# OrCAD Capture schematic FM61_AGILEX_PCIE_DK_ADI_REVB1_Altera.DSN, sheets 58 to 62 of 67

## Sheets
58 PWR - VCC_HSSI: size Custom
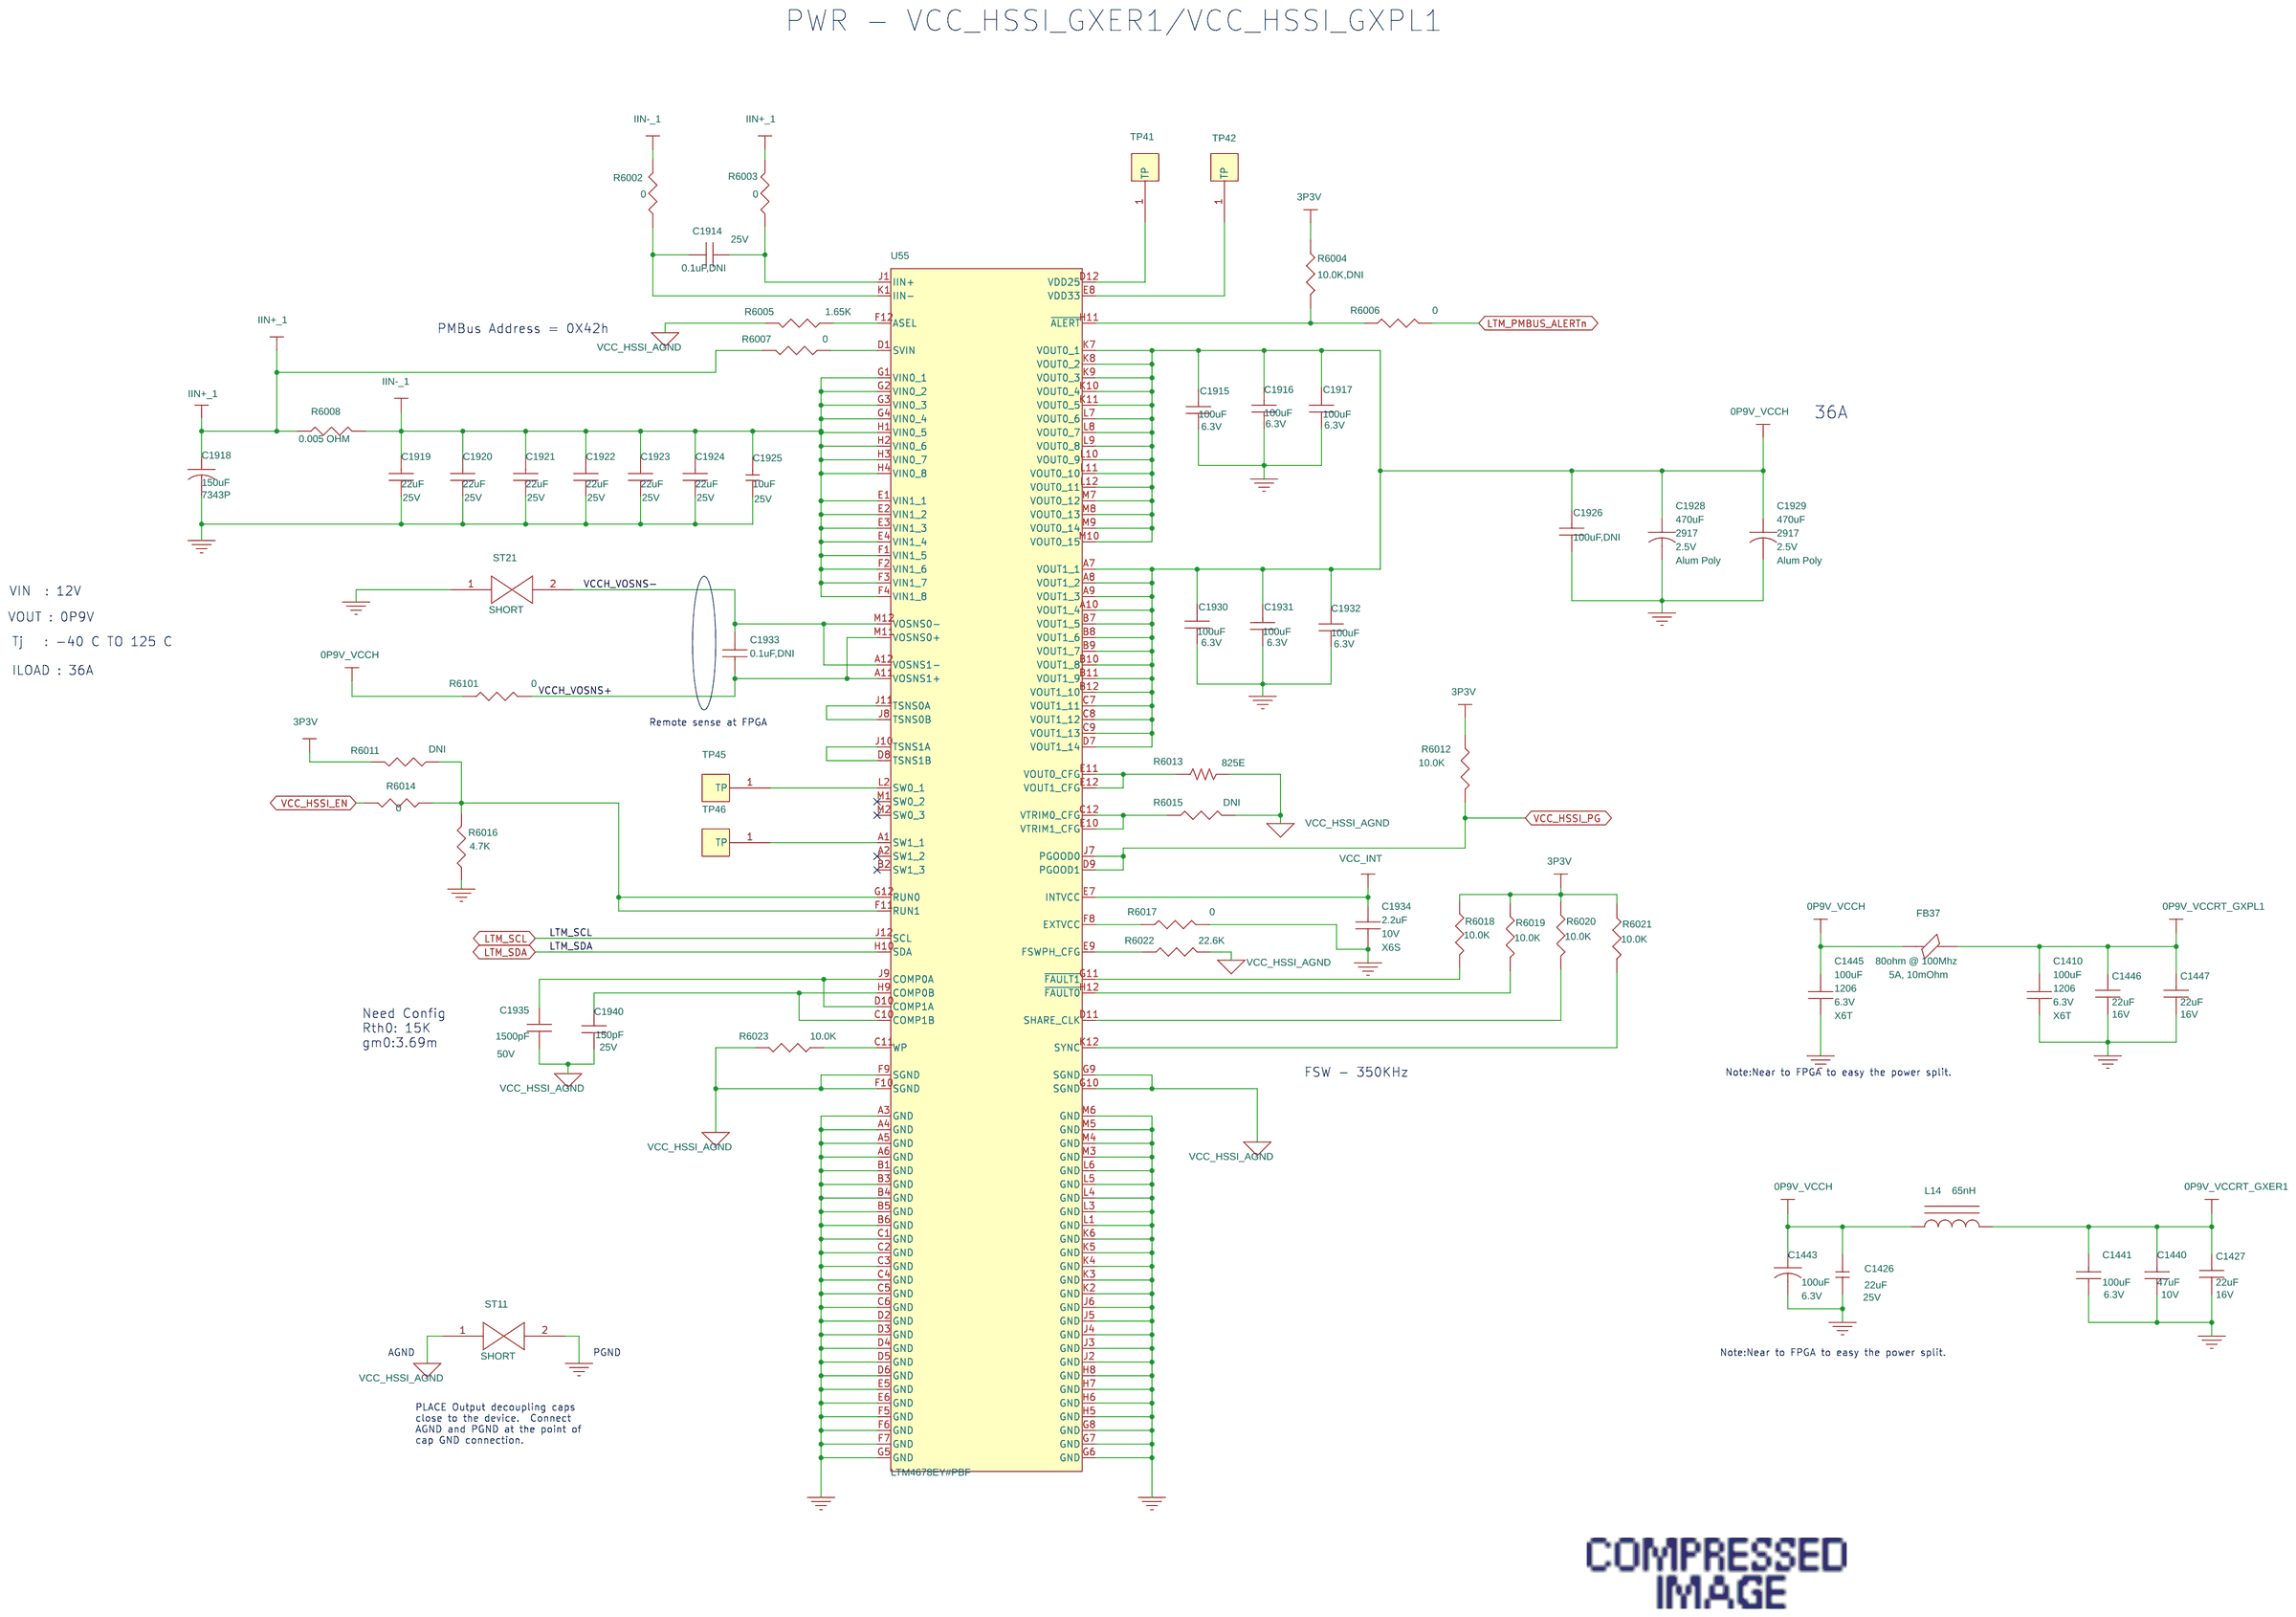
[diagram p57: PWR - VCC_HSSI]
59 PWR - 1p2V_VCCR: size B
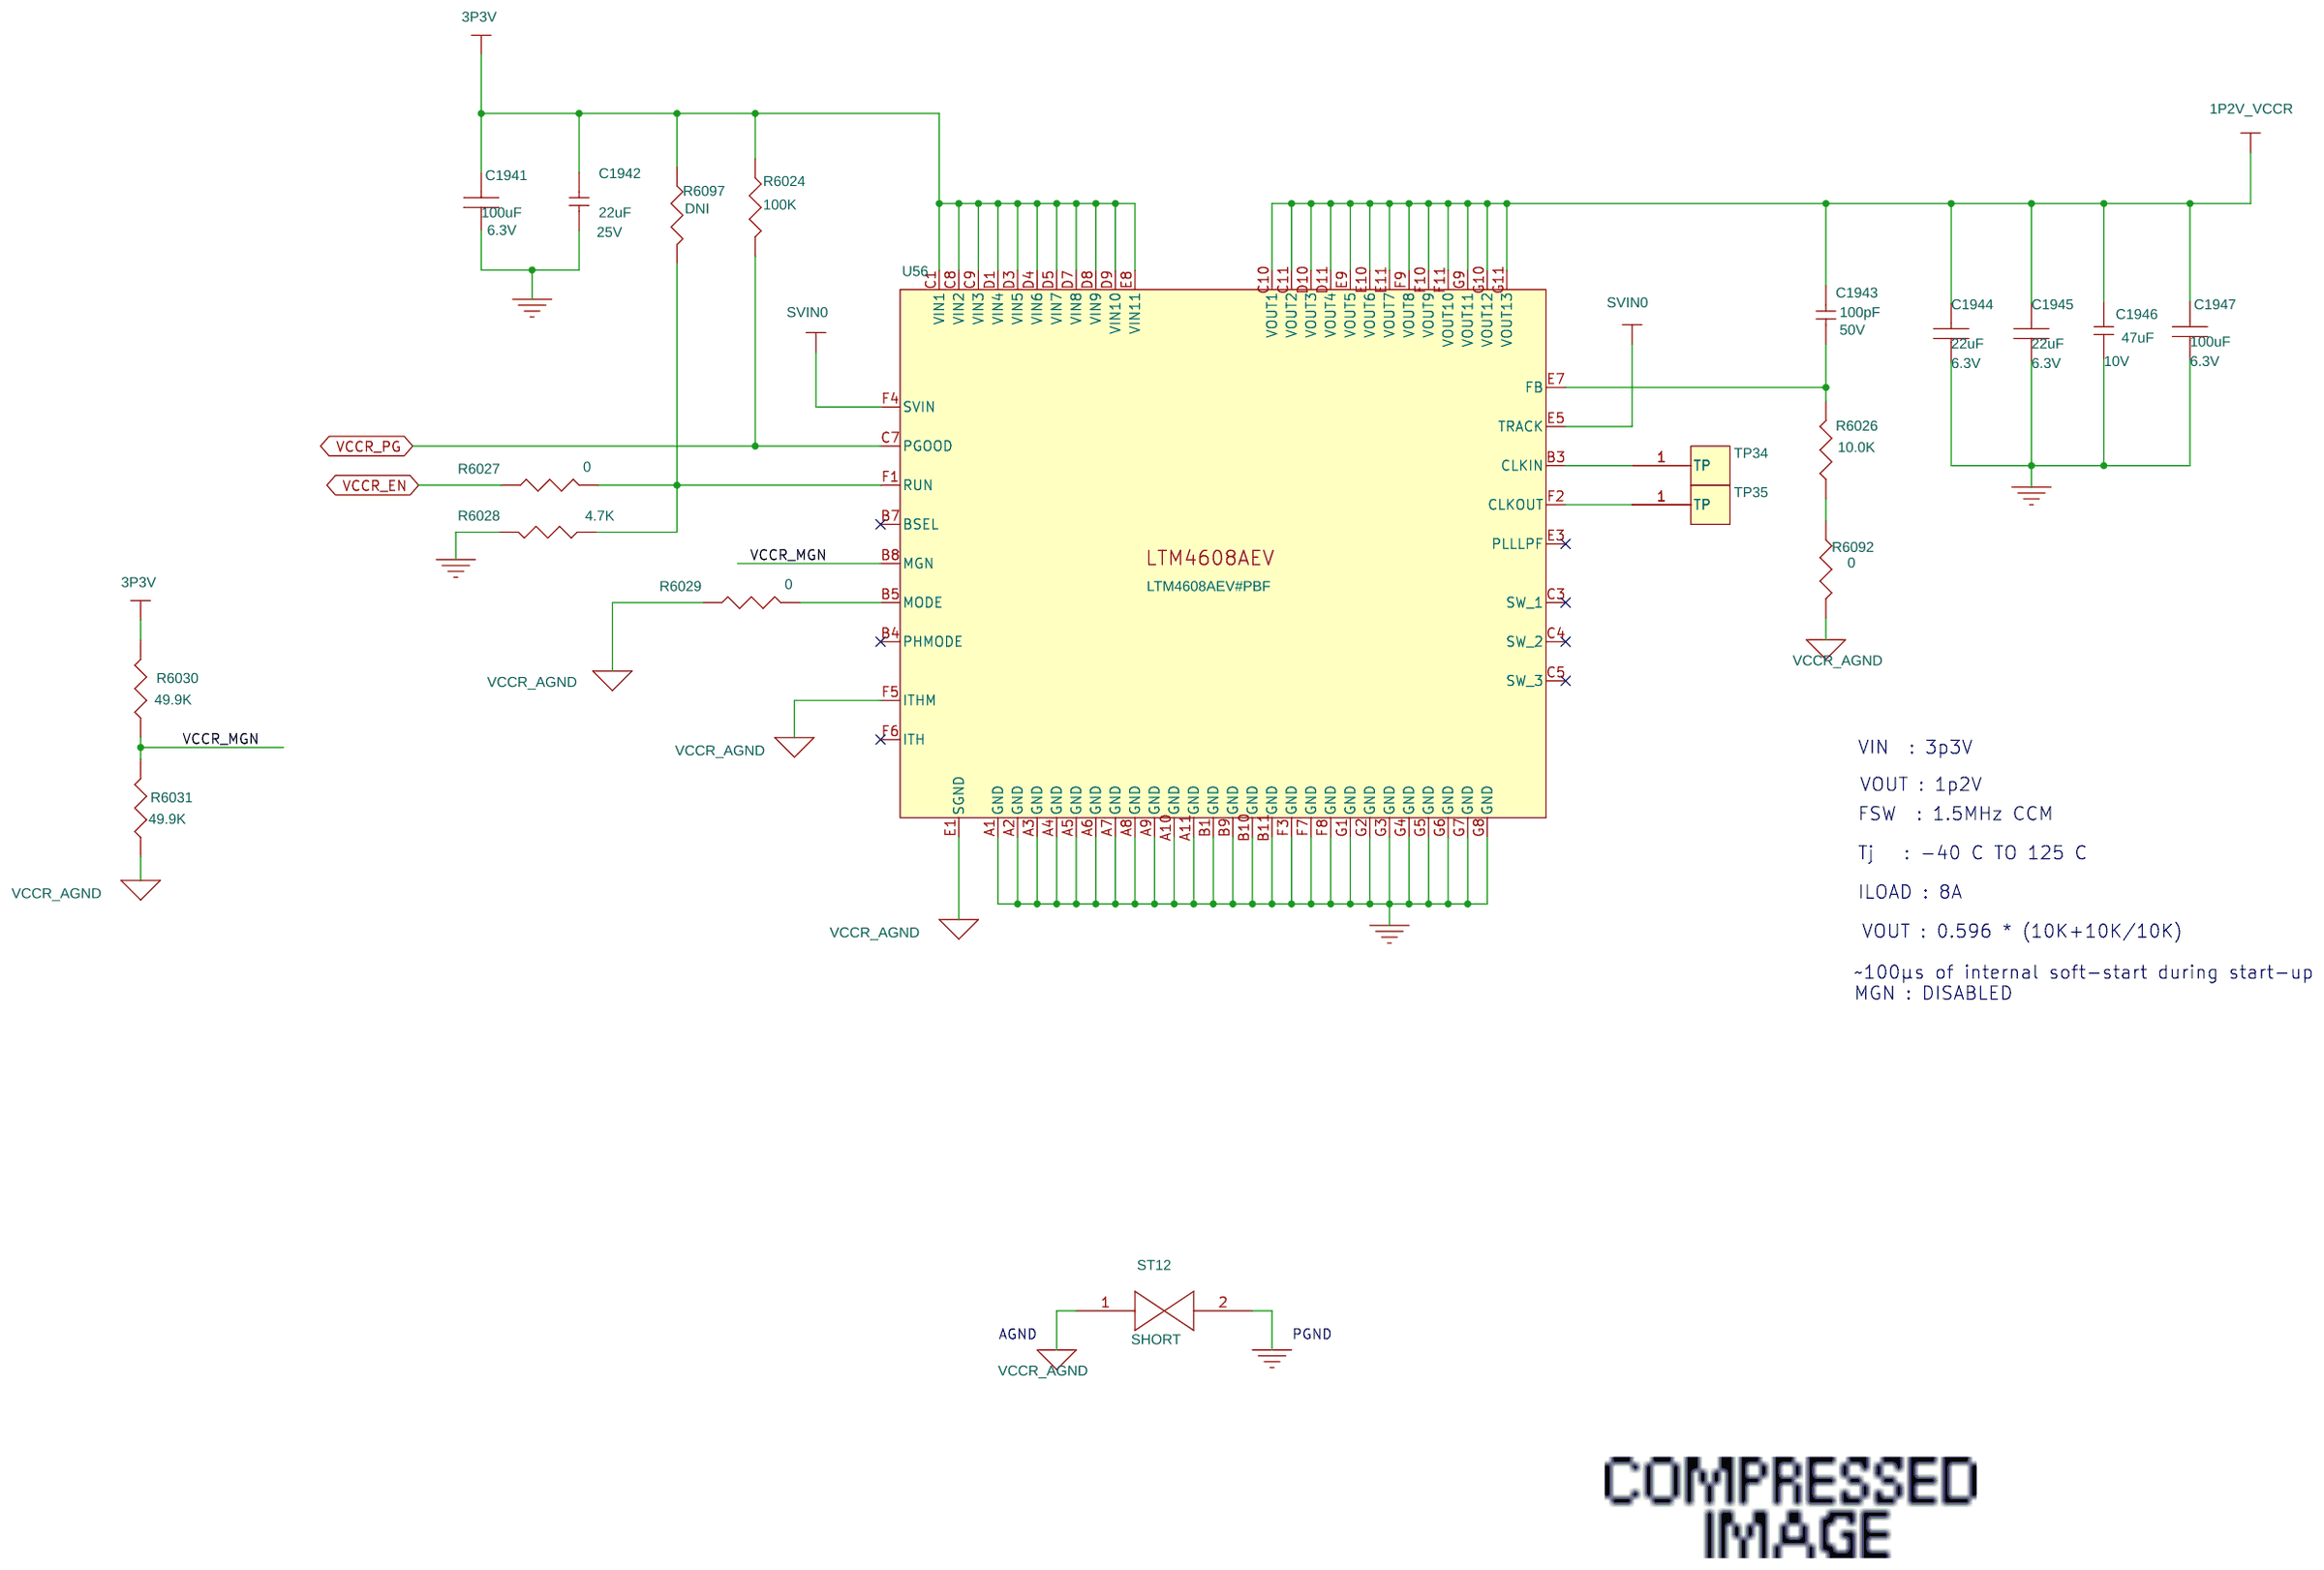
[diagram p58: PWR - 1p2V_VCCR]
60 PWR - 1p2V_DDR4_CH01: size B
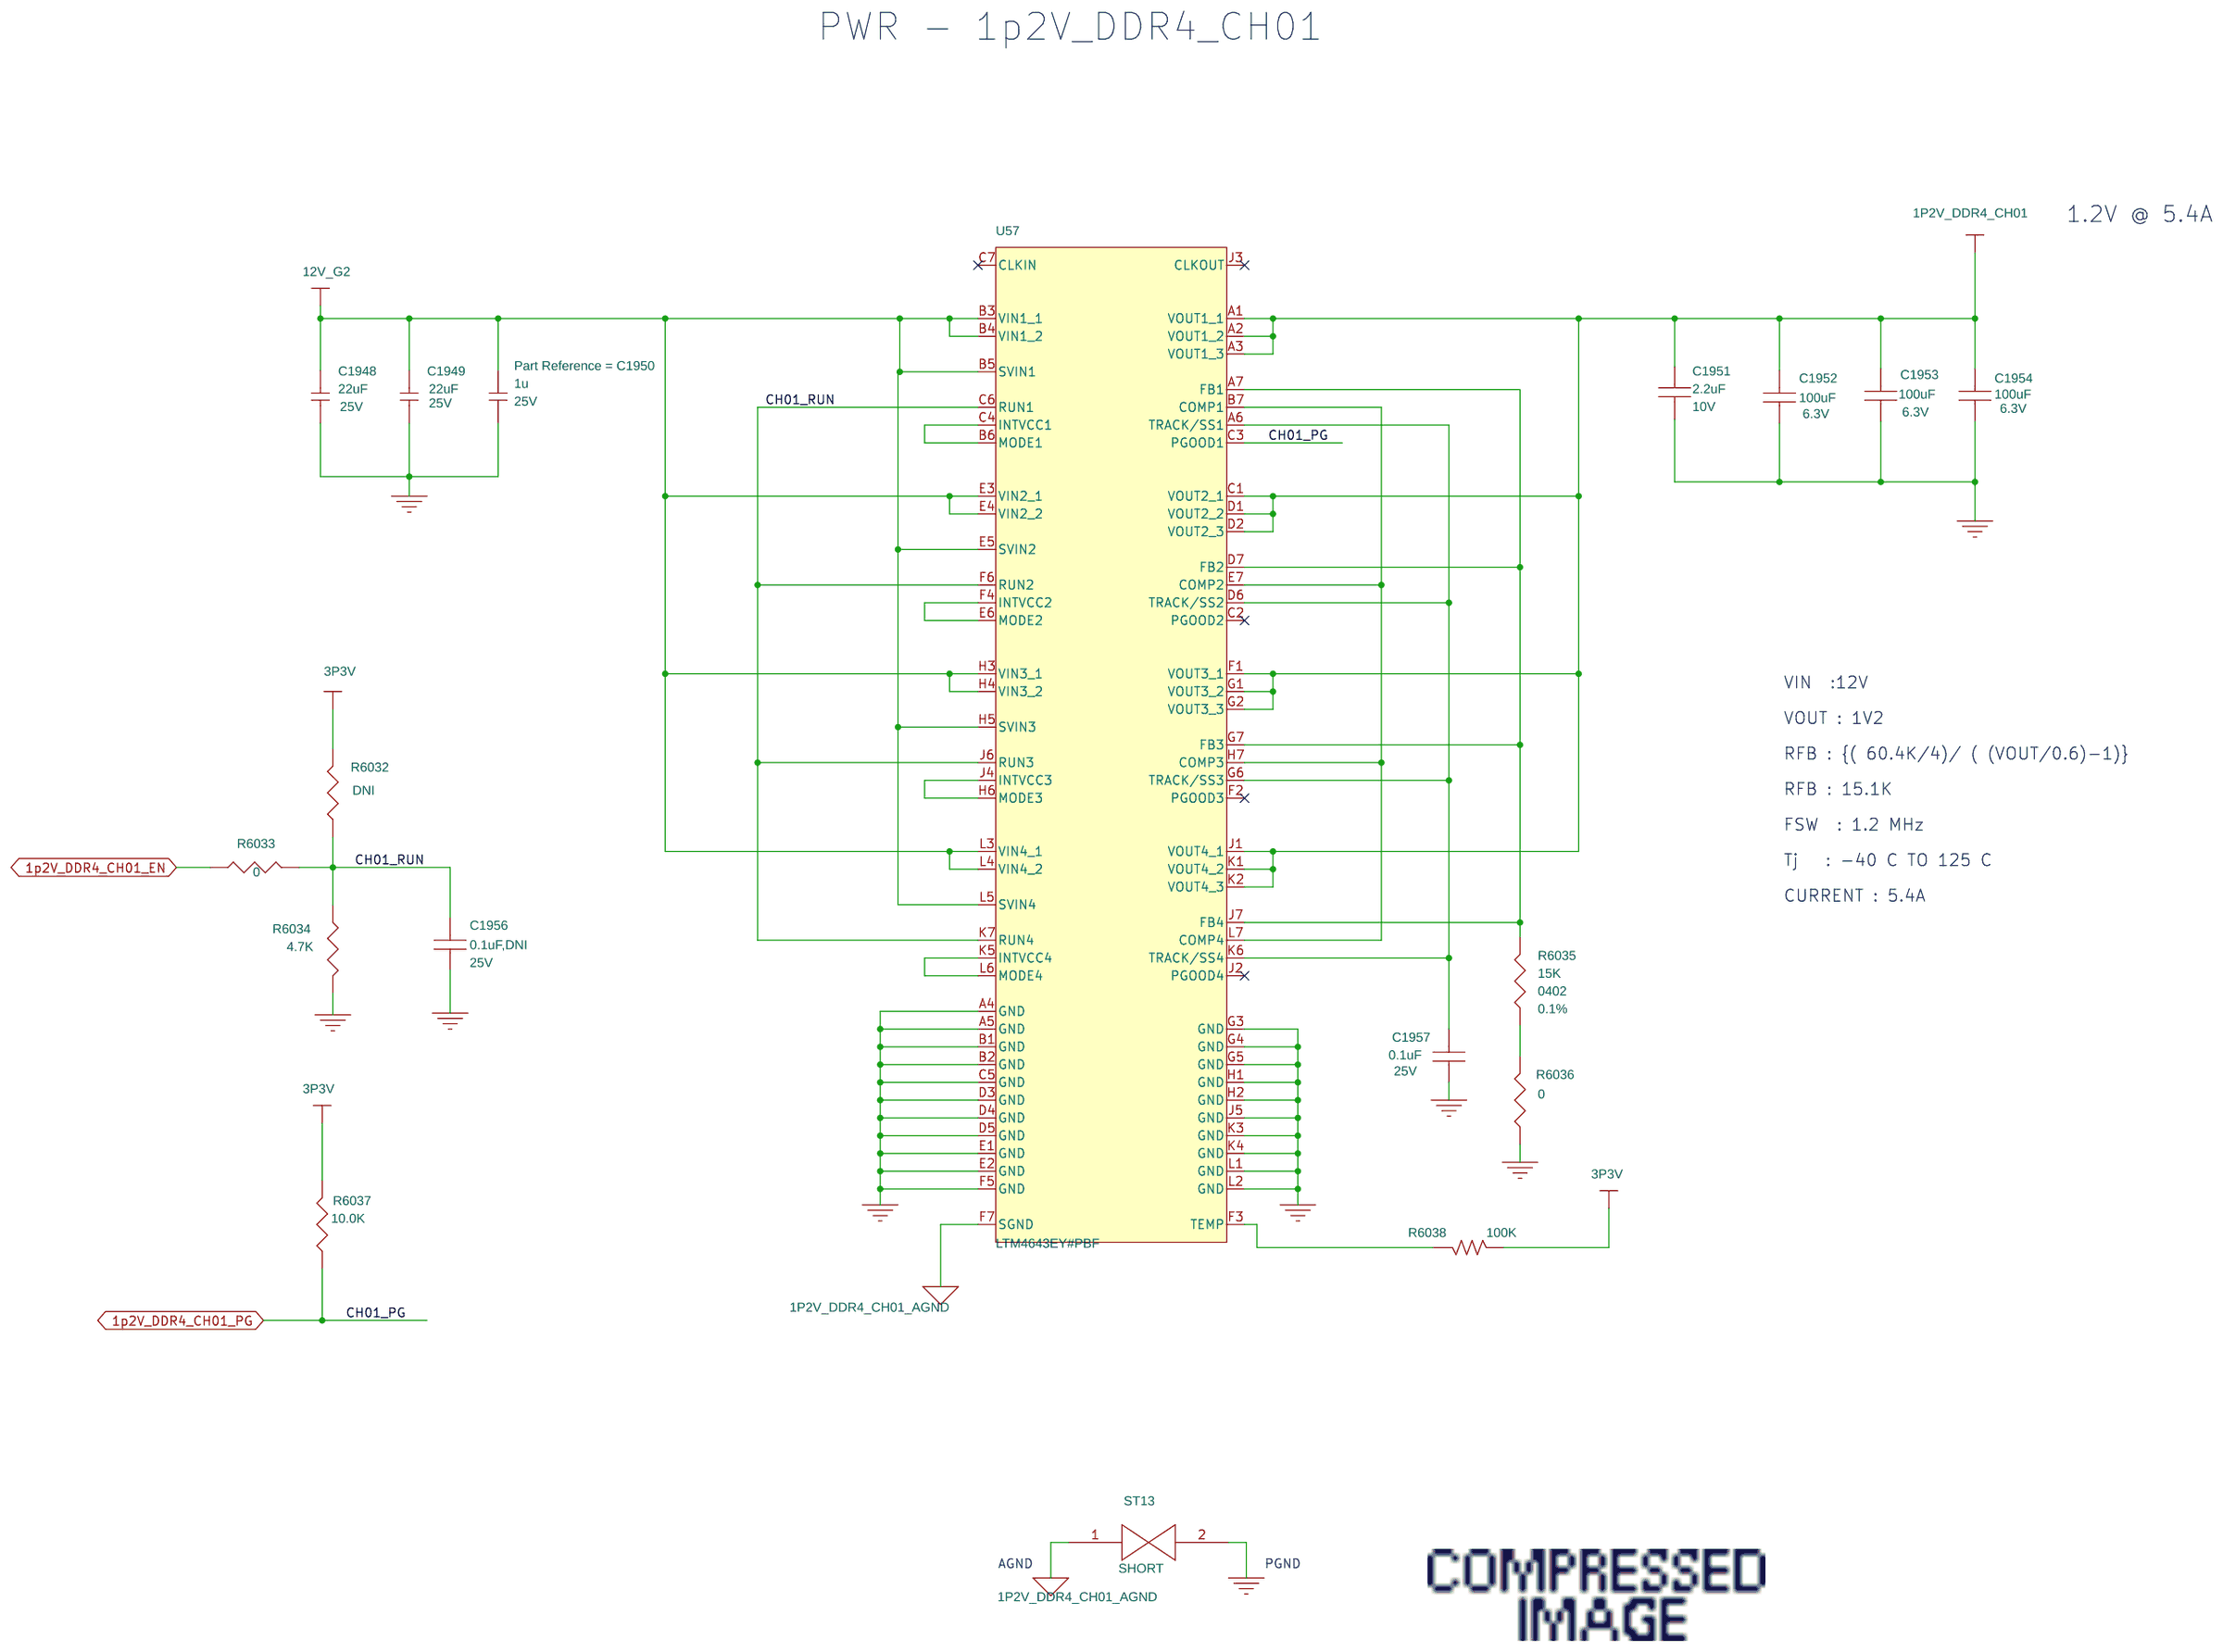
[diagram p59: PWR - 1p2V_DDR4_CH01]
61 PWR - 1p2V_DDR4_CH23: size B
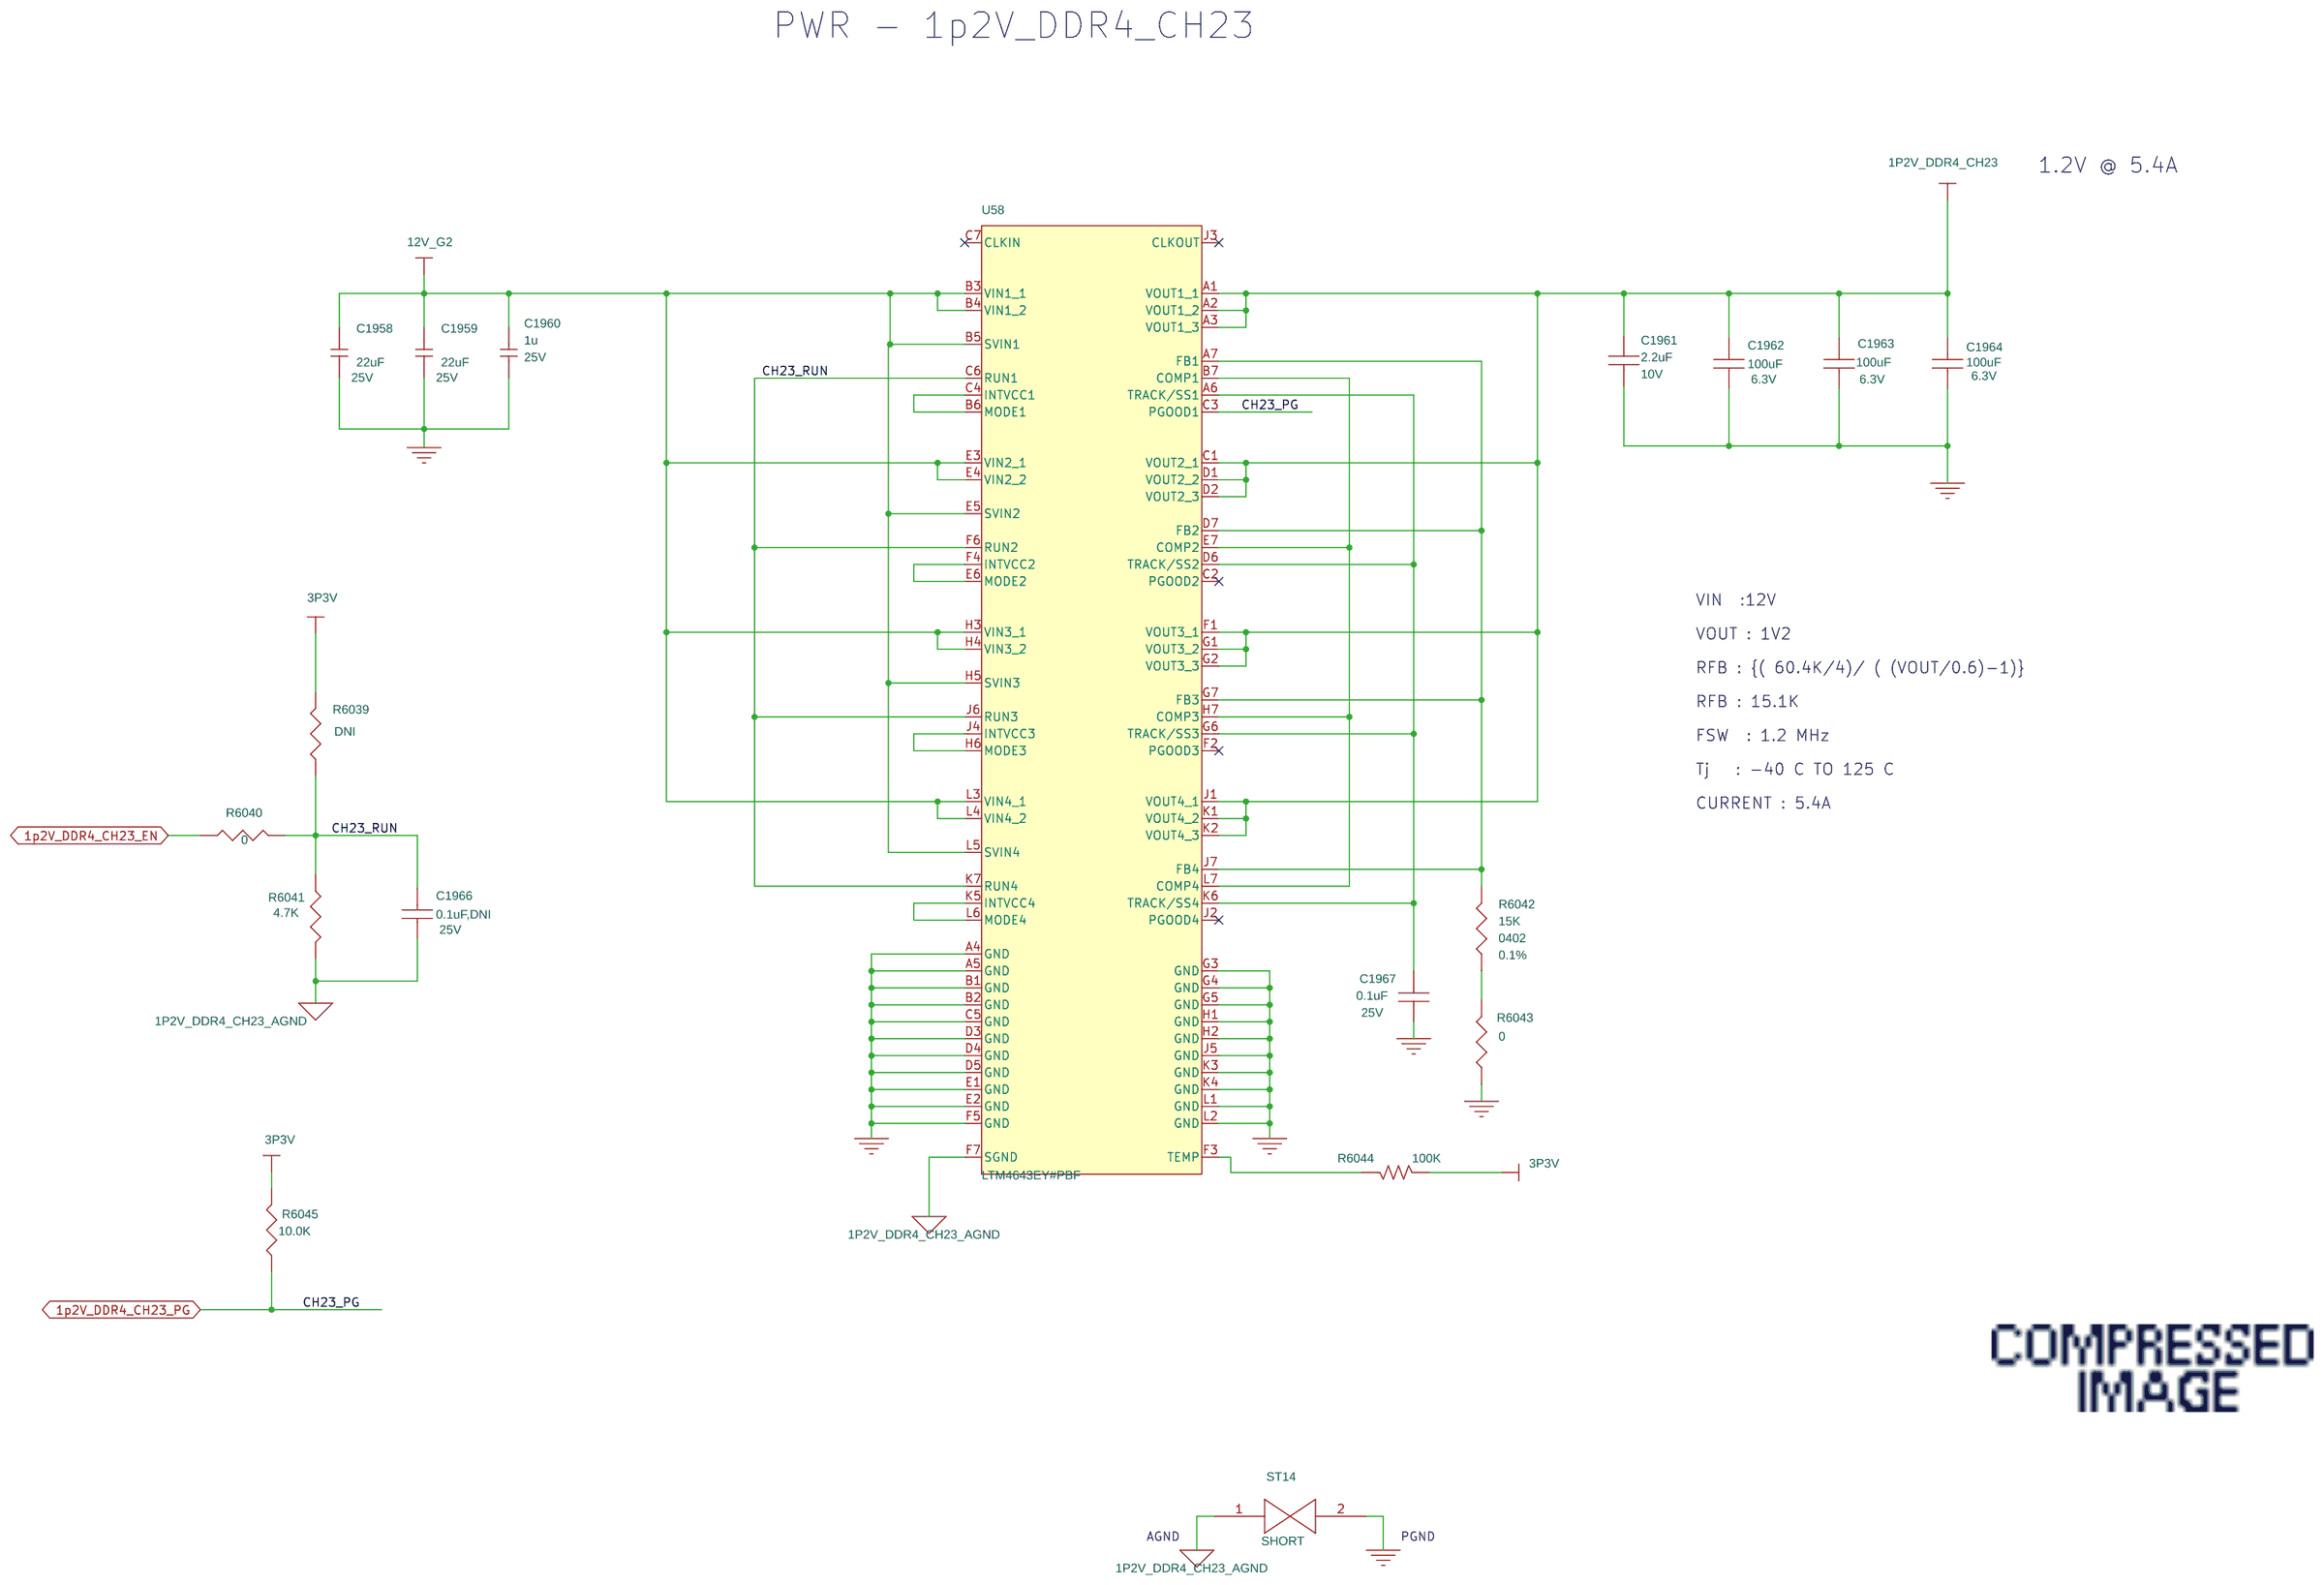
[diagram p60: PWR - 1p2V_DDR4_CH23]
62 PWR - 0p6V_VTT/VREF: size B
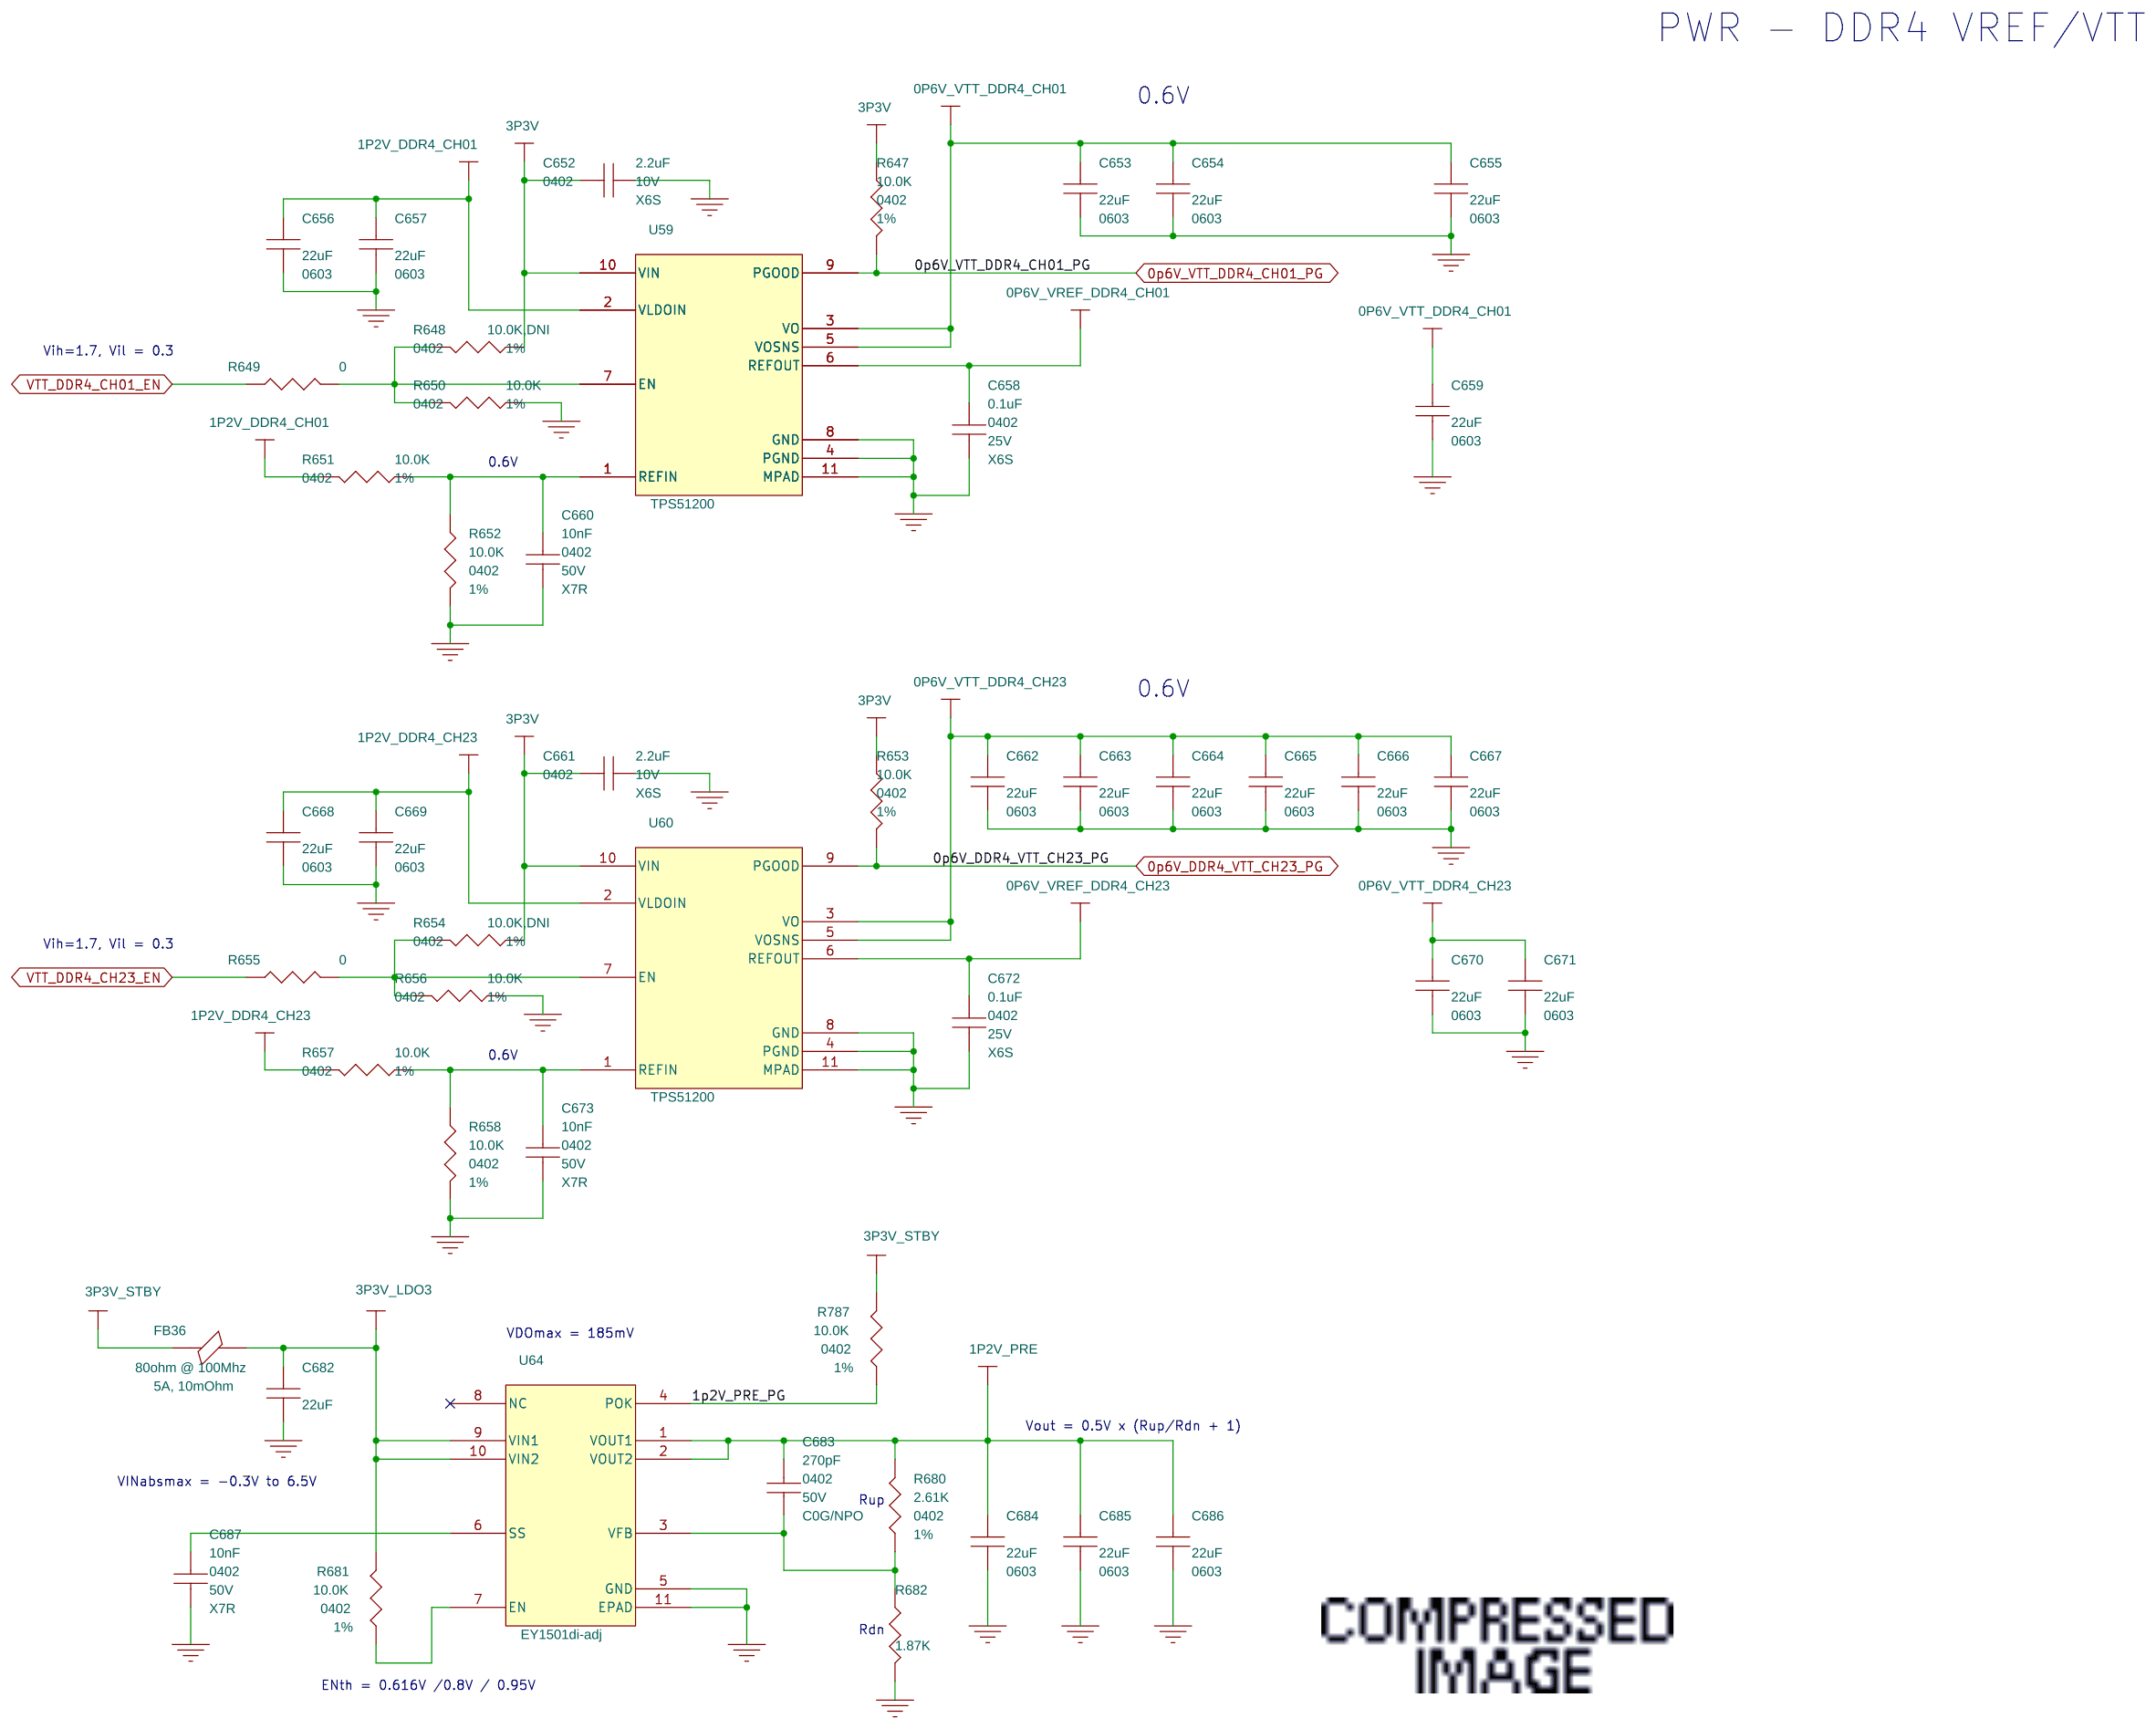
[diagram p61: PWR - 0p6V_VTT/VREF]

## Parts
sheet PWR - 0p6V_VTT/VREF
C652  2.2uF  [0402]
C653  22uF  [0603]
C654  22uF  [0603]
C655  22uF  [0603]
C656  22uF  [0603]
C657  22uF  [0603]
C658  0.1uF  [0402]
C659  22uF  [0603]
C660  10nF  [0402]
C661  2.2uF  [0402]
C662  22uF  [0603]
C663  22uF  [0603]
C664  22uF  [0603]
C665  22uF  [0603]
C666  22uF  [0603]
C667  22uF  [0603]
C668  22uF  [0603]
C669  22uF  [0603]
C670  22uF  [0603]
C671  22uF  [0603]
C672  0.1uF  [0402]
C673  10nF  [0402]
C682  22uF  [0603]
C683  270pF  [0402]
C684  22uF  [0603]
C685  22uF  [0603]
C686  22uF  [0603]
C687  10nF  [0402]
FB36  80ohm @ 100Mhz  [0805]
R647  10.0K  [0402]
R648  10.0K,DNI  [0402]
R649  0  [0402]
R650  10.0K  [0402]
R651  10.0K  [0402]
R652  10.0K  [0402]
R653  10.0K  [0402]
R654  10.0K,DNI  [0402]
R655  0  [0402]
R656  10.0K  [0402]
R657  10.0K  [0402]
R658  10.0K  [0402]
R680  2.61K  [0402]
R681  10.0K  [0402]
R682  1.87K  [0402]
R787  10.0K  [0402]
U59  TPS51200  [VSON-11]
U60  TPS51200  [VSON-11]
U64  EY1501di-adj  [DFN-11]
sheet PWR - 1p2V_DDR4_CH01
C1948  22uF  [1206]
C1949  22uF  [1206]
C1950  1u  [capc1005x60l20l]
C1951  2.2uF  [CC0603N]
C1952  100uF  [1206]
C1953  100uF  [1206]
C1954  100uF  [1206]
C1956  0.1uF,DNI  [0402]
C1957  0.1uF  [0402]
R6032  DNI  [0402]
R6033  0  [0402]
R6034  4.7K  [0402]
R6035  15K  [0402]
R6036  0  [0402]
R6037  10.0K  [0402]
R6038  100K  [R0402]
ST13  SHORT  [SHORT]
U57  LTM4643EY#PBF  [BGA77C127P7X11_900X1500X262N]
sheet PWR - 1p2V_DDR4_CH23
C1958  22uF  [1206]
C1959  22uF  [1206]
C1960  1u  [capc1005x60l20l]
C1961  2.2uF  [CC0603N]
C1962  100uF  [1206]
C1963  100uF  [1206]
C1964  100uF  [1206]
C1966  0.1uF,DNI  [0402]
C1967  0.1uF  [0402]
R6039  DNI  [0402]
R6040  0  [0402]
R6041  4.7K  [0402]
R6042  15K  [0402]
R6043  0  [0402]
R6044  100K  [R0402]
R6045  10.0K  [0402]
ST14  SHORT  [SHORT]
U58  LTM4643EY#PBF  [BGA77C127P7X11_900X1500X262N]
sheet PWR - 1p2V_VCCR
C1941  100uF  [1206]
C1942  22uF  [1206]
C1943  100pF  [0402]
C1944  22uF  [0603]
C1945  22uF  [0603]
C1946  47uF  [1206]
C1947  100uF  [1206]
R6024  100K  [0402]
R6026  10.0K  [0402]
R6027  0  [0402]
R6028  4.7K  [0402]
R6029  0  [0402]
R6030  49.9K  [0402]
R6031  49.9K  [0402]
R6092  0  [0402]
R6097  DNI  [0402]
ST12  SHORT  [SHORT]
TP34  TESTPOINT  [30mil_TP]
TP35  TESTPOINT  [30mil_TP]
U56  LTM4608AEV#PBF  [LGA68S127P7X11_900X1500X292]
sheet PWR - VCC_HSSI
C1410  100uF  [1206]
C1426  22uF  [1206]
C1427  22uF  [0805]
C1440  47uF  [0805]
C1441  100uF  [0805]
C1443  100uF  [B2]
C1445  100uF  [1206]
C1446  22uF  [0805]
C1447  22uF  [0805]
C1914  0.1uF,DNI  [0402]
C1915  100uF  [1206]
C1916  100uF  [1206]
C1917  100uF  [1206]
C1918  150uF  [7343P]
C1919  22uF  [1206]
C1920  22uF  [1206]
C1921  22uF  [1206]
C1922  22uF  [1206]
C1923  22uF  [1206]
C1924  22uF  [1206]
C1925  10uF  [1206]
C1926  100uF,DNI  [1206]
C1928  470uF  [2917]
C1929  470uF  [2917]
C1930  100uF  [1206]
C1931  100uF  [1206]
C1932  100uF  [1206]
C1933  0.1uF,DNI  [0402]
C1934  2.2uF  [0402]
C1935  1500pF  [0402]
C1940  150pF  [0402]
FB37  80ohm @ 100Mhz  [0805]
L14  65nH  [SL1616A-R06LU]
R6002  0  [0402]
R6003  0  [0402]
R6004  10.0K,DNI  [0402]
R6005  1.65K  [0402]
R6006  0  [0402]
R6007  0  [0402]
R6008  0.005 OHM  [RES_CSNL2512_0_005-0_006]
R6011  DNI  [0402]
R6012  10.0K  [0402]
R6013  825E  [0402]
R6014  0  [0402]
R6015  DNI  [0402]
R6016  4.7K  [0402]
R6017  0  [0402]
R6018  10.0K  [0402]
R6019  10.0K  [0402]
R6020  10.0K  [0402]
R6021  10.0K  [0402]
R6022  22.6K  [0402]
R6023  10.0K  [0402]
R6101  0  [0402]
ST11  SHORT  [SHORT]
ST21  SHORT  [SHORT]
TP41  TESTPOINT  [30mil_TP]
TP42  TESTPOINT  [30mil_TP]
TP45  TESTPOINT  [30mil_TP]
TP46  TESTPOINT  [30mil_TP]
U55  LTM4678EY#PBF  [BGA144C127P12X12_1600X1600X626]

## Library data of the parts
C652 C661 = CAP: CAP CER 2.2UF 10V X6S 0402; Dielectric: X6S; IPN: H90637-001; IPN No: H90637-001; Item Num: P03-17966R; LIFECYCLE_PHASE: Active; Lead Free Status: Lead Free; Manufacturer: Murata; Manufacturer Part Num: GRM155C81A225KE44D; Num Pins: 2; Part Class: CAPACITORS; RATED_VOLTAGE: 10V; RoHS Compliant: RoHS Compliant; Tolerance: 10%
C653-C657 C659 C662-C671 C684-C686 = CAP: CAP CER 22UF 6.3V X6S 0603; AGILE_LINK: http://sj-agile9app/Agile/PLMServlet?action=OpenEmailObject&classid=10000&objid=257560276; IPN: H63299-001; Item Num: P03-17963R; LIFECYCLE_PHASE: Active; Lead Free Status: Lead Free; MFR_LIFECYCLE: Active; Manufacturer: Murata; Manufacturer Part Num: GRM188C80J226ME15D; Num Pins: 2; PART_SUBCLASS: CAPACITORS; RATED_VOLTAGE: 6.3V; RoHS Compliant: RoHS Compliant; TOLERANCE: 20%; Temperature Coefficient: X6S
C658 C672 = CAP: CAP CER 0.1UF 25V X6S 0402; Dielectric: X6S; IPN: K19434-001; IPN No: K19434-001; Item Num: P03-17989R; LIFECYCLE_PHASE: Active; Lead Free Status: Lead Free; Manufacturer: Murata; Manufacturer Part Num: GRM155C81E104KA12D; Num Pins: 2; Part Class: CAPACITORS; RATED_VOLTAGE: 25V; RoHS Compliant: RoHS Compliant; Tolerance: 10%
C660 C673 C687 = CAP: CAP - CER, 10NF, 50V, +/-10%, X7R, 0402 SMD; CAPACITANCE: 0.1uF; Dielectric: X7R; IPN: A36096-100; Item Num: P03-16318R; LIFECYCLE_PHASE: Active; Lead Free Status: Lead Free; Manufacturer: Murata; Manufacturer Part Num: GRM155R71H103KA88D; Num Pins: 2; Part Class: CAPACITORS; RATED_VOLTAGE: 50V; RoHS Compliant: RoHS Compliant; Tolerance: 10%
C682 = CAP: CAP CER 22UF 6.3V X6S 0603; AGILE_LINK: http://sj-agile9app/Agile/PLMServlet?action=OpenEmailObject&classid=10000&objid=257560276; IPN: H63299-001; Item Num: P03-17963R; LIFECYCLE_PHASE: Active; Lead Free Status: Not Lead Free; MFR_LIFECYCLE: Active; Manufacturer: Murata; Manufacturer Part Num: GRM188C80J226ME15D; Num Pins: 2; PART_SUBCLASS: CAPACITORS; RATED_VOLTAGE: 6.3V; RoHS Compliant: RoHS Compliant; TOLERANCE: 20%; Temperature Coefficient: X6S
C683 = CAP: CAP - CERAMIC, 270PF 0402 50V 5% C0G; AGILE_LINK: http://sj-agile9app/Agile/PLMServlet?action=OpenEmailObject&classid=10000&objid=257560276; CAPACITANCE: 47pF; IPN: D70542-107; Item Num: P03-15059R; LIFECYCLE_PHASE: Active; Lead Free Status: Not Lead Free; MFR_LIFECYCLE: Active; Manufacturer: Murata; Manufacturer Part Num: GRM1555C1H271JA01D; Num Pins: 2; PART_SUBCLASS: CAPACITORS; RATED_VOLTAGE: 50V; RoHS Compliant: RoHS Compliant; TOLERANCE: 1%; Temperature Coefficient: C0G/NPO
FB36 FB37 = BEAD_FERRITE_SM: FERRITE BEAD 80 OHM 0805 1LN; IPN: G32678-001; Item Num: P04-17218R; LIFECYCLE_PHASE: Active; MFR_LIFECYCLE: Active; Manufacturer: Laird; Manufacturer Part Num: HI0805R800R-10; Num Pins: 2; PART_SUBCLASS: INDUCTORS; Part Class: Inductors; RoHS Compliant: Yes; Value2: 5A, 10mOhm
R647 R648 R650-R654 R656-R658 R681 R787 = RESISTOR: RES,10.0K OHMS,1.0%,1/16W, 0402; AGILE_LINK: http://sj-agile9app/Agile/PLMServlet?action=OpenEmailObject&classid=10000&objid=146548997; IPN: A93548-034; Item Num: P02-11364R; LIFECYCLE_PHASE: Active; Lead Free Status: No; MFR_LIFECYCLE: Active; Manufacturer: Panasonic; Manufacturer Part Num: ERJ-2RKF1002X; Num Pins: 2; PART_SUBCLASS: RESISTORS; POWER: 1/16W; RESISTANCE: 10K; RoHS Compliant: Yes; TOLERANCE: 1%
R649 R655 R6033 R6036 R6040 R6043 = RESISTOR: RES ZERO OHM 1/16W 5% 0402 SMD; IPN: H30887-001; Item Num: P02-14020R; Lead Free Status: No; Manufacturer: Panasonic; Manufacturer Part Num: ERJ-2GE0R00X; Num Pins: 2; Part Class: RESISTORS; RoHS Compliant: Yes; Tolerance: 5%
R680 = RESISTOR: RES - 2.61K OHM, 1%,1/10W, 0402 SMD; IPN: G41697-001; Item Num: P02-16710R; Lead Free Status: Yes; Manufacturer: Panasonic; Manufacturer Part Num: ERJ-2RKF2611x; Num Pins: 2; Part Class: RESISTORS; RoHS Compliant: Yes; TOLERANCE: 1%
R682 = RESISTOR: RES - 1.87K OHMS, 1.0%, 1/16W, 0402; IPN: K16301-001; Item Num: P02-16414R; Lead Free Status: No; Manufacturer: Vishay; Manufacturer Part Num: CRCW04021K87FKxx; Num Pins: 2; Part Class: Resistors
U59 U60 = TPS51200: IPN: H28999-001; Manufacturer Part Num: TPS51200DRCR
U64 = EY1501di-adj: IC,LIN,DFN,ISL80101-AD,VREF; IPN: H38446-001; Item Num: P01-18061R; Manufacturer: Intel/Enpirion; Manufacturer Part Num: ISL80101IRAJZ-T
C1426 C1942 C1948 C1949 C1958 C1959 = Cap,_NP,_1206: CAP - CER, 22UF, 25V, 10%, X5R, 1206; IPN: K28232-001; Item Num: P03-17640R; Manufacturer: Murata; Manufacturer Part Num: GRM31CR61E226KE15L; Voltage: 25V
C1950 C1960 = Cap,_NP,_0402: CAPC,X6S,0402,1.00UF,25V,+/- 10%; Agile Part Number: 11606; Dielectric: X5R/X6S; IPN: H81594-001; Manufacturer: Murata; Manufacturer Part Num: GRM155C81E105KE11D; Package: 0402; Part Number: GRM155C81E105KE11D; Structure: MLCC; Voltage: 25V
C1951 C1961 = CAP: CAP.,2.2uF,X7R,10V,20%,0603; CLASS: DISCRETE; Dielectric Type: X7R; FPLIST: CC0603N,CC0603L,CC0603M; IPN: E54182-001; Inventory Qty: 15202; Manufacturer: kemet; Manufacturer PN: GRM188R61A225KE34x; Manufacturer Part Num: GRM188R61A225KE34x; PART_NUMBER: 150-3503; Package Size: 0603; Rated Voltage: 10V; Tolerance: 20%
C1915-C1917 C1930-C1932 C1952-C1954 C1962-C1964 = CAP: CAP CER 100UF 6.3V X6T 1206; AGILE_LINK: http://sj-agile9app/Agile/PLMServlet?action=OpenEmailObject&classid=10000&objid=257560276; IPN: H65271-004; Item Num: P03-18002R; LIFECYCLE_PHASE: Active; Lead Free Status: Lead Free; MFR_LIFECYCLE: Active; Manufacturer: Murata; Manufacturer Part Num: GRM31CD80J107ME39L; Num Pins: 2; PART_SUBCLASS: CAPACITORS; RATED_VOLTAGE: 6.3V; RoHS Compliant: RoHS Compliant; TOLERANCE: 20%; Temperature Coefficient: X6T
C1914 C1956 C1966 = CAP: CAP CER 0.1UF 25V X6S 0402; CAPACITANCE: 0.1uF; Dielectric: X6S; IPN: K19434-001; IPN No: K19434-001; Item Num: P03-XXXXXR; LIFECYCLE_PHASE: Active; Lead Free Status: Lead Free; Manufacturer: Murata; Manufacturer Part Num: GRM155C81E104KA12D; Num Pins: 2; Part Class: CAPACITORS; RATED_VOLTAGE: 25V; RoHS Compliant: RoHS Compliant; Tolerance: 10%; Voltage: 25V
C1957 C1967 = CAP: CAP CER 0.1UF 25V X6S 0402; Dielectric: X6S; IPN: K19434-001; IPN No: K19434-001; Item Num: P03-XXXXXR; LIFECYCLE_PHASE: Active; Lead Free Status: Lead Free; Manufacturer: Murata; Manufacturer Part Num: GRM155C81E104KA12D; Num Pins: 2; Part Class: CAPACITORS; RATED_VOLTAGE: 25V; RoHS Compliant: RoHS Compliant; Tolerance: 10%; Voltage: 25V
R6011 R6015 R6032 R6039 R6097 = RESISTOR: RES ZERO OHM 1/16W 5% 0402 SMD; Altera Part No.: P02-14020R; IPN: H30887-001; Item Num: P02-14020R; Lead Free Status: No; Manufacturer: Panasonic; Manufacturer Part Num: ERJ-2GE0R00X; Num Pins: 2; Part Class: RESISTORS; Price: 0; RoHS Compliant: Yes; Tolerance: 5%
R6016 R6028 R6034 R6041 = RESISTOR: RES 4.7K OHM 1/16W 5% 0402 SMD; IPN: H30885-001; Item Num: P02-14032R; Lead Free Status: No; Manufacturer: Panasonic; Manufacturer Part Num: ERJ-2GEJ472X; Manufacturer's Part No.: ERJ-2GEJ472X; Num Pins: 2; Part Class: RESISTORS; Price: 0; RoHS Compliant: Yes
R6035 R6042 = RESISTOR: RES SMD 15K OHM 0.1% 1/10W 0402; Altera Part No.: P02-14020R; IPN: J59798-001; Item Num: P02-14020R; Lead Free Status: No; Manufacturer: Panasonic; Manufacturer Part Num: ERA2AEB153X; Num Pins: 2; Part Class: RESISTORS; Part Number: ERJ-2RKF1502X; Price: 0; RoHS Compliant: Yes; Tolerance: 0.1%
R6012 R6018-R6021 R6023 R6037 R6045 = RESISTOR: RES,10.0K OHMS,1.0%,1/16W, 0402; AGILE_LINK: http://sj-agile9app/Agile/PLMServlet?action=OpenEmailObject&classid=10000&objid=146548997; IPN: A93548-034; Item Num: P02-11364R; LIFECYCLE_PHASE: Active; Lead Free Status: No; MFR_LIFECYCLE: Active; Manufacturer: Panasonic; Manufacturer Part Num: ERJ-2RKF1002X; Num Pins: 2; PART_SUBCLASS: RESISTORS; POWER: 1/16W; RoHS Compliant: Yes; TOLERANCE: +/-1%
R6038 R6044 = Resistor,_0402: RES,100K OHMS,1.0%,1/16W,0402; IPN: E86804-001; Item Num: P02-11386R; Manufacturer: Panasonic; Manufacturer Part Num: ERJ-2RKF1003X; POWER: 1/16W; TOLERANCE: +/-1%
ST11-ST14 ST21 = SHORT
U57 U58 = LTM4643EY#PBF: IC, ULTRATHIN QUAD uMODULE REGULATOR, WITH CONFIGURABLE 3A OUTPUT ARRAY, BGA-77P, SMD; IPN: M75351-001
C1941 C1947 = CAP: CAP CER 100UF 6.3V X6T 1206; AGILE_LINK: http://sj-agile9app/Agile/PLMServlet?action=OpenEmailObject&classid=10000&objid=257560276; IPN: H65271-004; Item Num: P03-18002R; LIFECYCLE_PHASE: Active; Lead Free Status: Lead Free; MFR_LIFECYCLE: Active; Manufacturer: Murata; Manufacturer Part Num: GRM31CD80J107ME39L; Num Pins: 2; PART_SUBCLASS: CAPACITORS; RATED_VOLTAGE: 6.3V; RoHS Compliant: RoHS Compliant; TOLERANCE: 20%; Temperature Coefficient: X6T; Voltage: 6.3V
C1943 = Cap,_NP,_0402: CAPC,C0G,0402,100.000PF,50.000V,+/-5%; IPN: A36095-026; Item Num: P03-11677R; Manufacturer: Murata; Manufacturer Part Num: UMK105CG101JV-F; RATED_VOLTAGE: 50V; Voltage: 50V
C1944 C1945 = CAP: CAP CER 22UF 6.3V X6S 0603; AGILE_LINK: http://sj-agile9app/Agile/PLMServlet?action=OpenEmailObject&classid=10000&objid=257560276; IPN: H63299-001; Item Num: P03-17963R; LIFECYCLE_PHASE: Active; Lead Free Status: Not Lead Free; MFR_LIFECYCLE: Active; Manufacturer: Murata; Manufacturer Part Num: GRM188C80J226ME15D; Num Pins: 2; PART_SUBCLASS: CAPACITORS; RATED_VOLTAGE: 6.3V; RoHS Compliant: RoHS Compliant; TOLERANCE: 20%; Temperature Coefficient: X6S; Voltage: 6.3V
C1946 = Cap,_NP,_1206: CAP - CER 47UF 10V 20% X5R 1206; IPN: K13655-001; Item Num: P03-17644R; Manufacturer: TDK Electronics; Manufacturer Part Num: C3216X5R1A476M160AB; Voltage: 10V
R6024 = RESISTOR: RES,100K OHMS,1.0%,1/16W,0402; IPN: E86804-001; Item Num: P02-11386R; Lead Free Status: No; Manufacturer: Panasonic; Manufacturer Part Num: ERJ-2RKF1003X; Num Pins: 2; POWER: 1/16W; Part Class: Resistors; Price: 0; RoHS Compliant: Yes; TOLERANCE: +/-1%
R6026 = RESISTOR: RES,10.0K OHMS,1.0%,1/16W, 0402; IPN: A93548-034; Item Num: P02-11364R; Manufacturer: Panasonic; Manufacturer Part Num: ERJ-2RKF1002X; Price: 0; RoHS Compliant: RoHS Compliant
R6006 R6017 R6027 R6029 R6092 R6101 = RESISTOR: RES ZERO OHM 1/16W 5% 0402 SMD; Altera Part No.: P02-14020R; IPN: H30887-001; Item Num: P02-14020R; Lead Free Status: No; Manufacturer: Panasonic; Manufacturer Part Num: ERJ-2GE0R00X; Num Pins: 2; Part Class: RESISTORS; RoHS Compliant: Yes; Tolerance: 5%
R6030 R6031 = RESISTOR: RES SMD 49.9KOHM 0.1% 1/16W 0402; IPN: C79651-037; Item Num: P02-17979R; Manufacturer: Panasonic; Manufacturer Part Num: ERA-2AEB4992X
TP34 TP35 TP41 TP42 TP45 TP46 = TESTPOINT
U56 = LTM4608AEV#PBF_V1: IPN: E78633-001
C1410 C1445 = CAP: CAP CER 100UF 6.3V X6T 1206; AGILE_LINK: http://sj-agile9app/Agile/PLMServlet?action=OpenEmailObject&classid=10000&objid=257560276; IPN: H65271-004; Item Num: P03-18002R; LIFECYCLE_PHASE: Active; Lead Free Status: Not Lead Free; MFR_LIFECYCLE: Active; Manufacturer: Murata; Manufacturer Part Num: GRM31CD80J107ME39L; Num Pins: 2; PART_SUBCLASS: CAPACITORS; RATED_VOLTAGE: 6.3V; RoHS Compliant: RoHS Compliant; TOLERANCE: 20%; Temperature Coefficient: X6T
C1427 C1446 C1447 = CAP: CAP - CER, 22UF, 16V, 20%, X5R, 0805; AGILE_LINK: http://sj-agile9app/Agile/PLMServlet?action=OpenEmailObject&classid=10000&objid=257560276; IPN: H14974-002; Item Num: P03-17664R; LIFECYCLE_PHASE: Active; Lead Free Status: Not Lead Free; MFR_LIFECYCLE: Active; Manufacturer: TDK Electronics; Manufacturer Part Num: GRM21BR61C226ME44L; Num Pins: 2; PART_SUBCLASS: CAPACITORS; RATED_VOLTAGE: 16V; RoHS Compliant: RoHS Compliant; TOLERANCE: +/-10%; Voltage: 16V
C1440 = CAP: CAP - CER 47UF, 10V, 20%, X5R, +/-20%, 0805; AGILE_LINK: http://sj-agile9app/Agile/PLMServlet?action=OpenEmailObject&classid=10000&objid=257560276; IPN: 644066-136; Item Num: P03-17686R; LIFECYCLE_PHASE: Active; Lead Free Status: Not Lead Free; MFR_LIFECYCLE: Active; Manufacturer: TDK Electronics; Manufacturer Part Num: C2012X5R1A476M125AC; Num Pins: 2; PART_SUBCLASS: CAPACITORS; RATED_VOLTAGE: 6.3V; RoHS Compliant: RoHS Compliant; TOLERANCE: 20%; Temperature Coefficient: X5R; Voltage: 10V
C1441 = CAP: CAP CER 100UF 6.3V X5R 0805; AGILE_LINK: http://sj-agile9app/Agile/PLMServlet?action=OpenEmailObject&classid=10000&objid=257560276; IPN: K32109-001; Item Num: P03-17918R; LIFECYCLE_PHASE: Active; Lead Free Status: Lead Free; MFR_LIFECYCLE: Active; Manufacturer: Murata; Manufacturer Part Num: GRM21BR60J107ME15L; Num Pins: 2; PART_SUBCLASS: CAPACITORS; RATED_VOLTAGE: 6.3V; RoHS Compliant: RoHS Compliant; TOLERANCE: 20%; Temperature Coefficient: X6T; Voltage: 6.3V
C1443 = PCAP: CAP - POSCAP 100uF, 6.3V, ESR =.025 OHMS, B2; IPN: 724613-168; LIFECYCLE_PHASE: Active; Lead Free Status: Lead Free; MFR_LIFECYCLE: Active; Manufacturer: Panasonic; Manufacturer Part Num: 6TPE100MPB; Num Pins: 2; PART_SUBCLASS: CAPACITORS; RATED_VOLTAGE: 6.3V; RoHS Compliant: RoHS Compliant; Working Voltage: 6.3V
C1918 = PCAP: CAP - TANT POLYMER,150UF,16V,50MOHM ESR20%, 7343*1.8MM; IPN: G46681-001; Item Num: P03-17713R; LIFECYCLE_PHASE: Active; Lead Free Status: Lead Free; MFR_LIFECYCLE: Active; Manufacturer: Panasonic; Manufacturer Part Num: 16TQC150MYF; Num Pins: 2; PART_SUBCLASS: CAPACITORS; RATED_VOLTAGE: 16V; RoHS Compliant: RoHS Compliant; TOLERANCE: +/-20%
C1919-C1924 = CAP: CAP - CER, 22UF, 25V, 10%, X5R, 1206; Agile Part Number: P03-17640R; IPN: K28232-001; Item Num: P03-17640R; Lead Free Status: Yes; Manufacturer: Murata; Manufacturer Part Num: GRM31CR61E226KE15L; Num Pins: 2; Part Class: Capacitors; Price: 0; RoHS Compliant: Yes; Voltage: 25V
C1925 = Cap,_NP,_1206: CAP - CERAMIC, 10UF, 10%, X5R, 25V, 1206; Agile Part Number: P03-15063R; Dielectric: X7R; IPN: K28255-001; Item Num: P03-15063R; Manufacturer: TDK; Manufacturer Part Num: C3216X7R1E106K160AB; Part Number: C3216X7R1E106K160AB; TOLERANCE: ±10%; Voltage: 25V
C1926 = CAP: CAP CER 100UF 6.3V X6T 1206; AGILE_LINK: http://sj-agile9app/Agile/PLMServlet?action=OpenEmailObject&classid=10000&objid=257560276; CAPACITANCE: 100uF; IPN: H65271-004; Item Num: P03-18002R; LIFECYCLE_PHASE: Active; Lead Free Status: Lead Free; MFR_LIFECYCLE: Active; Manufacturer: Murata; Manufacturer Part Num: GRM31CD80J107ME39L; Num Pins: 2; PART_SUBCLASS: CAPACITORS; RATED_VOLTAGE: 6.3V; RoHS Compliant: RoHS Compliant; TOLERANCE: 20%; Temperature Coefficient: X6T
C1928 = PCAP: CAPS,AL-P,V,470.00uF,2.5V,+/- 20%,V,; AGILE_LINK: http://sj-agile9app/Agile/PLMServlet?action=OpenEmailObject&classid=10000&objid=257237054; IPN: K22160-001; IPN No: K22160-001; Item Num: P03-17853R; LIFECYCLE_PHASE: Active; Lead Free Status: Lead Free; MFR_LIFECYCLE: Active; Manufacturer: Panasonic; Manufacturer Part Num: EEF-GX0E471R; Num Pins: 2; PART_SUBCLASS: CAPACITORS; RATED_VOLTAGE: 2.5V; RoHS Compliant: RoHS Compliant; TOLERANCE: 20%; Type: Alum Poly; Voltage: 2.5V
C1929 = PCAP: CAPS,AL-P,V,470.00uF,2.5V,+/- 20%,V,; AGILE_LINK: http://sj-agile9app/Agile/PLMServlet?action=OpenEmailObject&classid=10000&objid=257237054; IPN: K22160-001; IPN No: K22160-001; Item Num: P03-18005R; LIFECYCLE_PHASE: Active; Lead Free Status: Lead Free; MFR_LIFECYCLE: Active; Manufacturer: Panasonic; Manufacturer Part Num: EEF-GX0E471R; Num Pins: 2; PART_SUBCLASS: CAPACITORS; RATED_VOLTAGE: 2.5V; RoHS Compliant: RoHS Compliant; TOLERANCE: 20%; Type: Alum Poly; Voltage: 2.5V
C1933 = CAP: CAP CER 0.1UF 25V X6S 0402; CAPACITANCE: 0.1uF; Dielectric: X6S; IPN: K19434-001; IPN No: K19434-001; Item Num: P03-XXXXXR; LIFECYCLE_PHASE: Active; Lead Free Status: Lead Free; Manufacturer: Murata; Manufacturer Part Num: GRM155C81E104KA12D; Num Pins: 2; Part Class: CAPACITORS; RATED_VOLTAGE: 25V; RoHS Compliant: RoHS Compliant; Tolerance: 10%
C1934 = CAP: CAP CER 2.2UF 10V X6S 0402; CAPACITANCE: 0.1uF; Dielectric: X6S; IPN: H90637-001; IPN No: H90637-001; Item Num: P03-17966R; LIFECYCLE_PHASE: Active; Lead Free Status: Lead Free; Manufacturer: Murata; Manufacturer Part Num: GRM155C81A225KE44D; Num Pins: 2; Part Class: CAPACITORS; RATED_VOLTAGE: 10V; RoHS Compliant: RoHS Compliant; Tolerance: 10%; Voltage: 10V
C1935 = CAP: CAP CER 1500PF 50V X7R 0402; CAPACITANCE: 0.1uF; Dielectric: X7R; IPN: H57680-001; Item Num: P03-17989R; LIFECYCLE_PHASE: Active; Lead Free Status: Lead Free; Manufacturer: AVX; Manufacturer Part Num: GRM155R71H152KA01D; Num Pins: 2; Part Class: CAPACITORS; RATED_VOLTAGE: 50V; RoHS Compliant: RoHS Compliant; Tolerance: 10%; Voltage: 50V
C1940 = CAP: CAP CER 150PF 25V C0G/NP0 0402; Dielectric: X6S; IPN: K28252-001; Item Num: P03-17989R; LIFECYCLE_PHASE: Active; Lead Free Status: Lead Free; Manufacturer: Murata; Manufacturer Part Num: GRM1555C1E151JA01D; Num Pins: 2; Part Class: CAPACITORS; RATED_VOLTAGE: 25V; RoHS Compliant: RoHS Compliant; Tolerance: 5%; Voltage: 25V
L14 = INDUCTOR_IRON: IND, 65nH; IPN: K64515-001; Manufacturer: Inter Technical Group
R6002 R6003 R6007 R6014 = RES_0_OHM_5%_1_16W_0402_SMD: IPN: H30887-001
R6004 = RESISTOR: RES,10.0K OHMS,1.0%,1/16W, 0402; AGILE_LINK: http://sj-agile9app/Agile/PLMServlet?action=OpenEmailObject&classid=10000&objid=146548997; IPN: A93548-034; Item Num: P02-11364R; LIFECYCLE_PHASE: Active; Lead Free Status: No; MFR_LIFECYCLE: Active; Manufacturer: Panasonic; Manufacturer Part Num: ERJ-2RKF1002X; Num Pins: 2; PART_SUBCLASS: RESISTORS; POWER: 1/16W; RESISTANCE: 10.0K; RoHS Compliant: Yes; TOLERANCE: +/-1%
R6005 = RES_0_OHM_5%_1_16W_0402_SMD: RES 1.65K OHM 1% 1/16W 0402; IPN: K15926-001; Manufacturer: PANASONIC; Manufacturer Part Num: ERJ-2RKF1651X
R6008 = CSNL2512FT5L00: IPN: M85067-001
R6013 = Resistor,_0402: RES SMD 825 OHM 0.1% 1/16W 0402; IPN: M79107-001; Item Num: P02-14408R; Manufacturer: Panasonic; Manufacturer Part Num: ERA-2AEB8250X; Part Number: ERA-2AEB8250X; Power: 1/16W; TOLERANCE: 0.1%
R6022 = RESISTOR: RES SMD 22.6KOHM 0.1% 1/16W 0402; IPN: G49062-001; Item Num: P02-17972R; Lead Free Status: No; Manufacturer: Panasonic; Manufacturer Part Num: ERA-2AEB2262X; Num Pins: 2; Part Class: Resistors; TOLERANCE: 0.1%
U55 = LTM4678EY#PBF: IPN: K21742-001

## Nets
12V_G1: C1918.1 R6003.2 R6007.1 R6008.1 ; also on sheet 9 12 15 18 47 48 51 52 53
12V_G2: C1948.2 C1949.2 C1950.1 C1958.2 C1959.2 C1960.1 U57.B3(VIN1_1) U57.B4(VIN1_2) U57.B5(SVIN1) U57.E3(VIN2_1) U57.E4(VIN2_2) U57.E5(SVIN2) U57.H3(VIN3_1) U57.H4(VIN3_2) U57.H5(SVIN3) U57.L3(VIN4_1) U57.L4(VIN4_2) U57.L5(SVIN4) U58.B3(VIN1_1) U58.B4(VIN1_2) U58.B5(SVIN1) U58.E3(VIN2_1) U58.E4(VIN2_2) U58.E5(SVIN2) U58.H3(VIN3_1) U58.H4(VIN3_2) U58.H5(SVIN3) U58.L3(VIN4_1) U58.L4(VIN4_2) U58.L5(SVIN4) ; also on sheet 45 48 49 50 54 55 57 63 64
GND: C652.1 C653.2 C654.2 C655.2 C656.2 C657.2 C658.2 C659.2 C660.2 C661.1 C662.2 C663.2 C664.2 C665.2 C666.2 C667.2 C668.2 C669.2 C670.2 C671.2 C672.2 C673.2 C682.2 C684.2 C685.2 C686.2 C687.2 C1410.1 C1426.1 C1427.2 C1440.1 C1441.1 C1443.2 C1445.1 C1446.2 C1447.2 C1915.1 C1916.1 C1917.1 C1918.2 C1919.1 C1920.1 C1921.1 C1922.1 C1923.1 C1924.1 C1925.1 C1926.1 C1928.2 C1929.2 C1930.1 C1931.1 C1932.1 C1934.2 C1941.1 C1942.1 C1944.1 C1945.1 C1946.2 C1947.1 C1948.1 C1949.1 C1950.2 C1951.2 C1952.1 C1953.1 C1954.1 C1956.1 C1957.1 C1958.1 C1959.1 C1960.2 C1961.2 C1962.1 C1963.1 C1964.1 C1967.1 R650.1 R652.2 R656.1 R658.2 R682.1 R6016.1 R6017.1 R6028.2 R6034.1 R6036.2 R6043.2 ST11.2 ST12.2 ST13.2 ST14.2 ST21.1 U55.A3(GND) U55.A4(GND) U55.A5(GND) U55.A6(GND) U55.B1(GND) U55.B3(GND) U55.B4(GND) U55.B5(GND) U55.B6(GND) U55.C1(GND) U55.C2(GND) U55.C3(GND) U55.C4(GND) U55.C5(GND) U55.C6(GND) U55.D2(GND) U55.D3(GND) U55.D4(GND) U55.D5(GND) U55.D6(GND) U55.E5(GND) U55.E6(GND) U55.F5(GND) U55.F6(GND) U55.F7(GND) U55.G5(GND) U55.G6(GND) U55.G7(GND) U55.G8(GND) U55.H5(GND) U55.H6(GND) U55.H7(GND) U55.H8(GND) U55.J2(GND) U55.J3(GND) U55.J4(GND) U55.J5(GND) U55.J6(GND) U55.K2(GND) U55.K3(GND) U55.K4(GND) U55.K5(GND) U55.K6(GND) U55.L1(GND) U55.L3(GND) U55.L4(GND) U55.L5(GND) U55.L6(GND) U55.M3(GND) U55.M4(GND) U55.M5(GND) U55.M6(GND) U56.A1(GND) U56.A2(GND) U56.A3(GND) U56.A4(GND) U56.A5(GND) U56.A6(GND) U56.A7(GND) U56.A8(GND) U56.A9(GND) U56.A10(GND) U56.A11(GND) U56.B1(GND) U56.B9(GND) U56.B10(GND) U56.B11(GND) U56.F3(GND) U56.F7(GND) U56.F8(GND) U56.G1(GND) U56.G2(GND) U56.G3(GND) U56.G4(GND) U56.G5(GND) U56.G6(GND) U56.G7(GND) U56.G8(GND) U57.A4(GND) U57.A5(GND) U57.B1(GND) U57.B2(GND) U57.C5(GND) U57.D3(GND) U57.D4(GND) U57.D5(GND) U57.E1(GND) U57.E2(GND) U57.F5(GND) U57.G3(GND) U57.G4(GND) U57.G5(GND) U57.H1(GND) U57.H2(GND) U57.J5(GND) U57.K3(GND) U57.K4(GND) U57.L1(GND) U57.L2(GND) U58.A4(GND) U58.A5(GND) U58.B1(GND) U58.B2(GND) U58.C5(GND) U58.D3(GND) U58.D4(GND) U58.D5(GND) U58.E1(GND) U58.E2(GND) U58.F5(GND) U58.G3(GND) U58.G4(GND) U58.G5(GND) U58.H1(GND) U58.H2(GND) U58.J5(GND) U58.K3(GND) U58.K4(GND) U58.L1(GND) U58.L2(GND) U59.4(PGND) U59.8(GND) U59.11(MPAD) U60.4(PGND) U60.8(GND) U60.11(MPAD) U64.5(GND) U64.11(EPAD) ; also on sheet 9 11 12 13 14 15 17 18 20 21 22 23 24 25 26 28 29 30 31 32 34 35 36 37 38 39 40 41 42 43 44 45 46 47 48 49 50 51 52 53 54 55 56 57 63 64 65 66
SVIN0: U56.E5(TRACK) U56.F4(SVIN)
VCC_HSSI_AGND: C1935.2 C1940.2 R6005.1 R6013.2 R6015.1 R6022.1 R6023.2 ST11.1 U55.F9(SGND) U55.F10(SGND) U55.G9(SGND) U55.G10(SGND)
VCC_HSSI_EN: R6014.1 ; also on sheet 46
VCC_HSSI_PG: R6012.1 U55.D9(PGOOD1) U55.J7(PGOOD0) ; also on sheet 46
VCC_INT: C1934.1 U55.E7(INTVCC)
VCCH_VOSNS+: C1933.1 R6101.1 U55.A11(VOSNS1+) U55.M11(VOSNS0+)
VCCH_VOSNS-: C1933.2 ST21.2 U55.A12(VOSNS1-) U55.M12(VOSNS0-)
VCCR_AGND: R6029.1 R6031.1 R6092.2 ST12.1 U56.E1(SGND) U56.F5(ITHM)
VCCR_EN: R6027.1 ; also on sheet 46
VCCR_MGN: R6030.1 R6031.2 U56.B8(MGN)
VCCR_PG: R6024.1 U56.C7(PGOOD) ; also on sheet 46
0p6V_DDR4_VTT_CH23_PG: R653.2 U60.9(PGOOD) ; also on sheet 46
0p6V_VREF_DDR4_CH01: C658.1 U59.6(REFOUT) ; also on sheet 9 12 34
0p6V_VREF_DDR4_CH23: C672.1 U60.6(REFOUT) ; also on sheet 15 18 34
0p6V_VTT_DDR4_CH01: C653.1 C654.1 C655.1 C659.1 U59.3(VO) U59.5(VOSNS) ; also on sheet 9 12
0p6V_VTT_DDR4_CH01_PG: R647.2 U59.9(PGOOD) ; also on sheet 46
0p6V_VTT_DDR4_CH23: C662.1 C663.1 C664.1 C665.1 C666.1 C667.1 C670.1 C671.1 U60.3(VO) U60.5(VOSNS) ; also on sheet 15 18
0p9V_VCCH: C1426.2 C1443.1 C1445.2 C1915.2 C1916.2 C1917.2 C1926.2 C1928.1 C1929.1 C1930.2 C1931.2 C1932.2 FB37.2 L14.1 R6101.2 U55.A7(VOUT1_1) U55.A8(VOUT1_2) U55.A9(VOUT1_3) U55.A10(VOUT1_4) U55.B7(VOUT1_5) U55.B8(VOUT1_6) U55.B9(VOUT1_7) U55.B10(VOUT1_8) U55.B11(VOUT1_9) U55.B12(VOUT1_10) U55.C7(VOUT1_11) U55.C8(VOUT1_12) U55.C9(VOUT1_13) U55.D7(VOUT1_14) U55.K7(VOUT0_1) U55.K8(VOUT0_2) U55.K9(VOUT0_3) U55.K10(VOUT0_4) U55.K11(VOUT0_5) U55.L7(VOUT0_6) U55.L8(VOUT0_7) U55.L9(VOUT0_8) U55.L10(VOUT0_9) U55.L11(VOUT0_10) U55.L12(VOUT0_11) U55.M7(VOUT0_12) U55.M8(VOUT0_13) U55.M9(VOUT0_14) U55.M10(VOUT0_15) ; also on sheet 34 46 66
0p9V_VCCRT_GXER1: C1427.1 C1440.2 C1441.2 L14.2 ; also on sheet 34 65
0p9V_VCCRT_GXPL1: C1410.2 C1446.1 C1447.1 FB37.1 ; also on sheet 34 66
1p2V_DDR4_CH01: C656.1 C657.1 C1951.1 C1952.2 C1953.2 C1954.2 R651.2 U57.A1(VOUT1_1) U57.A2(VOUT1_2) U57.A3(VOUT1_3) U57.C1(VOUT2_1) U57.D1(VOUT2_2) U57.D2(VOUT2_3) U57.F1(VOUT3_1) U57.G1(VOUT3_2) U57.G2(VOUT3_3) U57.J1(VOUT4_1) U57.K1(VOUT4_2) U57.K2(VOUT4_3) U59.2(VLDOIN) ; also on sheet 9 12 13 34 40 42 46 66
1p2V_DDR4_CH01_AGND: ST13.1 U57.F7(SGND)
1p2V_DDR4_CH01_EN: R6033.2 ; also on sheet 46
1p2V_DDR4_CH01_PG: R6037.1 U57.C3(PGOOD1) ; also on sheet 46
1p2V_DDR4_CH23: C668.1 C669.1 C1961.1 C1962.2 C1963.2 C1964.2 R657.2 U58.A1(VOUT1_1) U58.A2(VOUT1_2) U58.A3(VOUT1_3) U58.C1(VOUT2_1) U58.D1(VOUT2_2) U58.D2(VOUT2_3) U58.F1(VOUT3_1) U58.G1(VOUT3_2) U58.G2(VOUT3_3) U58.J1(VOUT4_1) U58.K1(VOUT4_2) U58.K2(VOUT4_3) U60.2(VLDOIN) ; also on sheet 15 16 18 19 25 34 46 66
1p2V_DDR4_CH23_AGND: C1966.1 R6041.1 ST14.1 U58.F7(SGND)
1p2V_DDR4_CH23_EN: R6040.2 ; also on sheet 46
1p2V_DDR4_CH23_PG: R6045.1 U58.C3(PGOOD1) ; also on sheet 46
1p2V_PRE: C683.2 C684.1 C685.1 C686.1 R680.2 U64.1(VOUT1) U64.2(VOUT2) ; also on sheet 41 44
1p2V_PRE_PG: R787.2 U64.4(POK)
1p2V_VCCR: C1943.1 C1944.2 C1945.2 C1946.1 C1947.2 U56.C10(VOUT1) U56.C11(VOUT2) U56.D10(VOUT3) U56.D11(VOUT4) U56.E9(VOUT5) U56.E10(VOUT6) U56.E11(VOUT7) U56.F9(VOUT8) U56.F10(VOUT9) U56.F11(VOUT10) U56.G9(VOUT11) U56.G10(VOUT12) U56.G11(VOUT13) ; also on sheet 34 65
3p3V: C652.2 C661.2 C1941.2 C1942.2 R647.1 R648.1 R653.1 R654.1 R6004.1 R6011.2 R6012.2 R6018.1 R6019.1 R6020.1 R6021.1 R6024.2 R6030.2 R6032.2 R6037.2 R6038.2 R6039.2 R6044.2 R6045.2 R6097.1 U56.C1(VIN1) U56.C8(VIN2) U56.C9(VIN3) U56.D1(VIN4) U56.D3(VIN5) U56.D4(VIN6) U56.D5(VIN7) U56.D7(VIN8) U56.D8(VIN9) U56.D9(VIN10) U56.E8(VIN11) U59.10(VIN) U60.10(VIN) ; also on sheet 46 50 51 54 55 56 57 63 64
3p3V_LDO3: C682.1 FB36.1 R681.1 U64.9(VIN1) U64.10(VIN2)
3p3V_STBY: FB36.2 R787.1 ; also on sheet 25 39 41 43 44 46 47 48 49
CH01_RUN: C1956.2 R6032.1 R6033.1 R6034.2 U57.C6(RUN1) U57.F6(RUN2) U57.J6(RUN3) U57.K7(RUN4)
CH23_RUN: C1966.2 R6039.1 R6040.1 R6041.2 U58.C6(RUN1) U58.F6(RUN2) U58.J6(RUN3) U58.K7(RUN4)
IIN-_1: C1919.2 C1920.2 C1921.2 C1922.2 C1923.2 C1924.2 C1925.2 R6002.2 R6008.2 U55.E1(VIN1_1) U55.E2(VIN1_2) U55.E3(VIN1_3) U55.E4(VIN1_4) U55.F1(VIN1_5) U55.F2(VIN1_6) U55.F3(VIN1_7) U55.F4(VIN1_8) U55.G1(VIN0_1) U55.G2(VIN0_2) U55.G3(VIN0_3) U55.G4(VIN0_4) U55.H1(VIN0_5) U55.H2(VIN0_6) U55.H3(VIN0_7) U55.H4(VIN0_8)
LTM_PMBUS_ALERTn: R6006.1 ; also on sheet 43 46 54
LTM_SCL: U55.J12(SCL) ; also on sheet 50 54
LTM_SDA: U55.H10(SDA) ; also on sheet 50 54
VTT_DDR4_CH01_EN: R649.2 ; also on sheet 46
VTT_DDR4_CH23_EN: R655.2 ; also on sheet 46
N36316045: R648.2 R649.1 R650.2 U59.7(EN)
N36316148: C660.1 R651.1 R652.1 U59.1(REFIN)
N36316465: R654.2 R655.1 R656.2 U60.7(EN)
N36316589: C673.1 R657.1 R658.1 U60.1(REFIN)
N36398138: C683.1 R680.1 R682.2 U64.3(VFB)
N36398140: C687.1 U64.6(SS)
N36398214: R681.2 U64.7(EN)
N40894339: C1914.2 R6002.1 U55.K1(IIN-)
N40894341: C1914.1 R6003.1 U55.J1(IIN+)
N40894343: TP41.1(TP) U55.D12(VDD25)
N40894345: TP42.1(TP) U55.E8(VDD33)
N40894542: R6004.2 R6006.2 U55.H11(~{ALERT})
N40894561: R6005.2 U55.F12(ASEL)
N40894590: R6007.2 U55.D1(SVIN)
N40895169: U55.J8(TSNS0B) U55.J11(TSNS0A)
N40895207: R6011.1 R6014.2 R6016.2 U55.F11(RUN1) U55.G12(RUN0)
N40895215: U55.D8(TSNS1B) U55.J10(TSNS1A)
N40895254: R6013.1 U55.E11(VOUT0_CFG) U55.E12(VOUT1_CFG)
N40895294: R6015.2 U55.C12(VTRIM0_CFG) U55.E10(VTRIM1_CFG)
N40895381: R6017.2 U55.F8(EXTVCC)
N40895450: R6022.2 U55.E9(FSWPH_CFG)
N40895467: C1935.1 U55.D10(COMP1A) U55.J9(COMP0A)
N40895475: R6018.2 U55.G11(~{FAULT1})
N40895479: R6019.2 U55.H12(~{FAULT0})
N40895481: R6020.2 U55.D11(SHARE_CLK)
N40895483: R6021.2 U55.K12(SYNC)
N40895485: C1940.1 U55.C10(COMP1B) U55.H9(COMP0B)
N40895537: R6023.1 U55.C11(WP)
N40899627: R6027.2 R6028.1 R6097.2 U56.F1(RUN)
N40899752: C1943.2 R6026.2 U56.E7(FB)
N40899813: TP34.1(TP) U56.B3(CLKIN)
N40899850: TP35.1(TP) U56.F2(CLKOUT)
N40899884: R6029.2 U56.B5(MODE)
N40903465: R6035.2 U57.A7(FB1) U57.D7(FB2) U57.G7(FB3) U57.J7(FB4)
N40903501: U57.B7(COMP1) U57.E7(COMP2) U57.H7(COMP3) U57.L7(COMP4)
N40903513: U57.B6(MODE1) U57.C4(INTVCC1)
N40903517: C1957.2 U57.A6(TRACK/SS1) U57.D6(TRACK/SS2) U57.G6(TRACK/SS3) U57.K6(TRACK/SS4)
N40903590: U57.E6(MODE2) U57.F4(INTVCC2)
N40903670: U57.H6(MODE3) U57.J4(INTVCC3)
N40903761: U57.K5(INTVCC4) U57.L6(MODE4)
N40903799: R6035.1 R6036.1
N40903928: R6038.1 U57.F3(TEMP)
N40907421: R6042.2 U58.A7(FB1) U58.D7(FB2) U58.G7(FB3) U58.J7(FB4)
N40907472: U58.B7(COMP1) U58.E7(COMP2) U58.H7(COMP3) U58.L7(COMP4)
N40907476: U58.B6(MODE1) U58.C4(INTVCC1)
N40907480: C1967.2 U58.A6(TRACK/SS1) U58.D6(TRACK/SS2) U58.G6(TRACK/SS3) U58.K6(TRACK/SS4)
N40907555: U58.E6(MODE2) U58.F4(INTVCC2)
N40907635: U58.H6(MODE3) U58.J4(INTVCC3)
N40907725: U58.K5(INTVCC4) U58.L6(MODE4)
N40907761: R6042.1 R6043.1
N40907881: R6044.1 U58.F3(TEMP)
N41038344: R6026.1 R6092.1
N41930528: TP45.1(TP) U55.L2(SW0_1)
N41930530: TP46.1(TP) U55.A1(SW1_1)

Not connected (* = marked no-connect by the designer): U55 A2(SW1_2)* B2(SW1_3)* M1(SW0_2)* M2(SW0_3)*; U56 B4(PHMODE)* B7(BSEL)* C3(SW_1)* C4(SW_2)* C5(SW_3)* E3(PLLLPF)* F6(ITH)*; U57 C2(PGOOD2)* C7(CLKIN)* F2(PGOOD3)* J2(PGOOD4)* J3(CLKOUT)*; U58 C2(PGOOD2)* C7(CLKIN)* F2(PGOOD3)* J2(PGOOD4)* J3(CLKOUT)*; U64 8(NC)*

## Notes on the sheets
sheet 58
- PWR - VCC_HSSI_GXER1/VCC_HSSI_GXPL1
- PMBus Address = 0X42h
- 36A
- VIN  : 12V
- VOUT : 0P9V
- Tj   : -40 C TO 125 C
- ILOAD : 36A
- Remote sense at FPGA
- Need Config
  Rth0: 15K
  gm0:3.69m
- FSW - 350KHz
- Note:Near to FPGA to easy the power split.
- AGND
- PGND
- Note:Near to FPGA to easy the power split.
- PLACE Output decoupling caps
  close to the device.  Connect
  AGND and PGND at the point of
  cap GND connection.
sheet 59
- VIN  : 3p3V
- VOUT : 1p2V
- FSW  : 1.5MHz CCM
- Tj   : -40 C TO 125 C
- ILOAD : 8A
- VOUT : 0.596 * (10K+10K/10K)
- ~100µs of internal soft-start during start-up
  MGN : DISABLED
- AGND
- PGND
sheet 60
- PWR - 1p2V_DDR4_CH01
- 1.2V @ 5.4A
- VIN  :12V
- VOUT : 1V2
- RFB : {( 60.4K/4)/ ( (VOUT/0.6)-1)}
- RFB : 15.1K
- FSW  : 1.2 MHz
- Tj   : -40 C TO 125 C
- CURRENT : 5.4A
- AGND
- PGND
sheet 61
- PWR - 1p2V_DDR4_CH23
- 1.2V @ 5.4A
- VIN  :12V
- VOUT : 1V2
- RFB : {( 60.4K/4)/ ( (VOUT/0.6)-1)}
- RFB : 15.1K
- FSW  : 1.2 MHz
- Tj   : -40 C TO 125 C
- CURRENT : 5.4A
- AGND
- PGND
sheet 62
- PWR - DDR4 VREF/VTT
- 0.6V
- Vih=1.7, Vil = 0.3
- 0.6V
- 0.6V
- Vih=1.7, Vil = 0.3
- 0.6V
- VDOmax = 185mV
- Vout = 0.5V x (Rup/Rdn + 1)
- VINabsmax = -0.3V to 6.5V
- Rup
- Rdn
- ENth = 0.616V /0.8V / 0.95V
